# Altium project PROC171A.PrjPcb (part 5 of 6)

## Sheet PROC171_Ehernet_RJ45_2.SchDoc
size 431 x 279 mm; Date: Not shown in title block; ApprovedBy: Not shown in title block; CheckedBy: Not shown in title block; Author: Not shown in title block; CompanyName: Not shown in title block; Engineer: Not shown in title block; Organization: Not shown in title block; Address1: Not shown in title block; Address2: Not shown in title block; Address3: Not shown in title block; Address4: Not shown in title block; DocumentNumber: 20; Revision: Use project parameter SCH_Rev; SheetNumber: 20; SheetTotal: 27; PageSetup: Record=PageOptions¦CenterHorizontal=True¦CenterVertical=True¦PrintScale=1.00¦XCorrection=1.00¦YCorrection=1.00¦PrintKind=0¦BorderSize=5000000¦LeftOffset=0¦BottomOffset=0¦Orientation=2¦PaperLength=1000¦PaperWidth=1000¦Scale=100¦PaperSource=15¦PrintQuality=600¦MediaType=1¦DitherType=10¦PaperKind=Letter¦PrintScaleMode=1
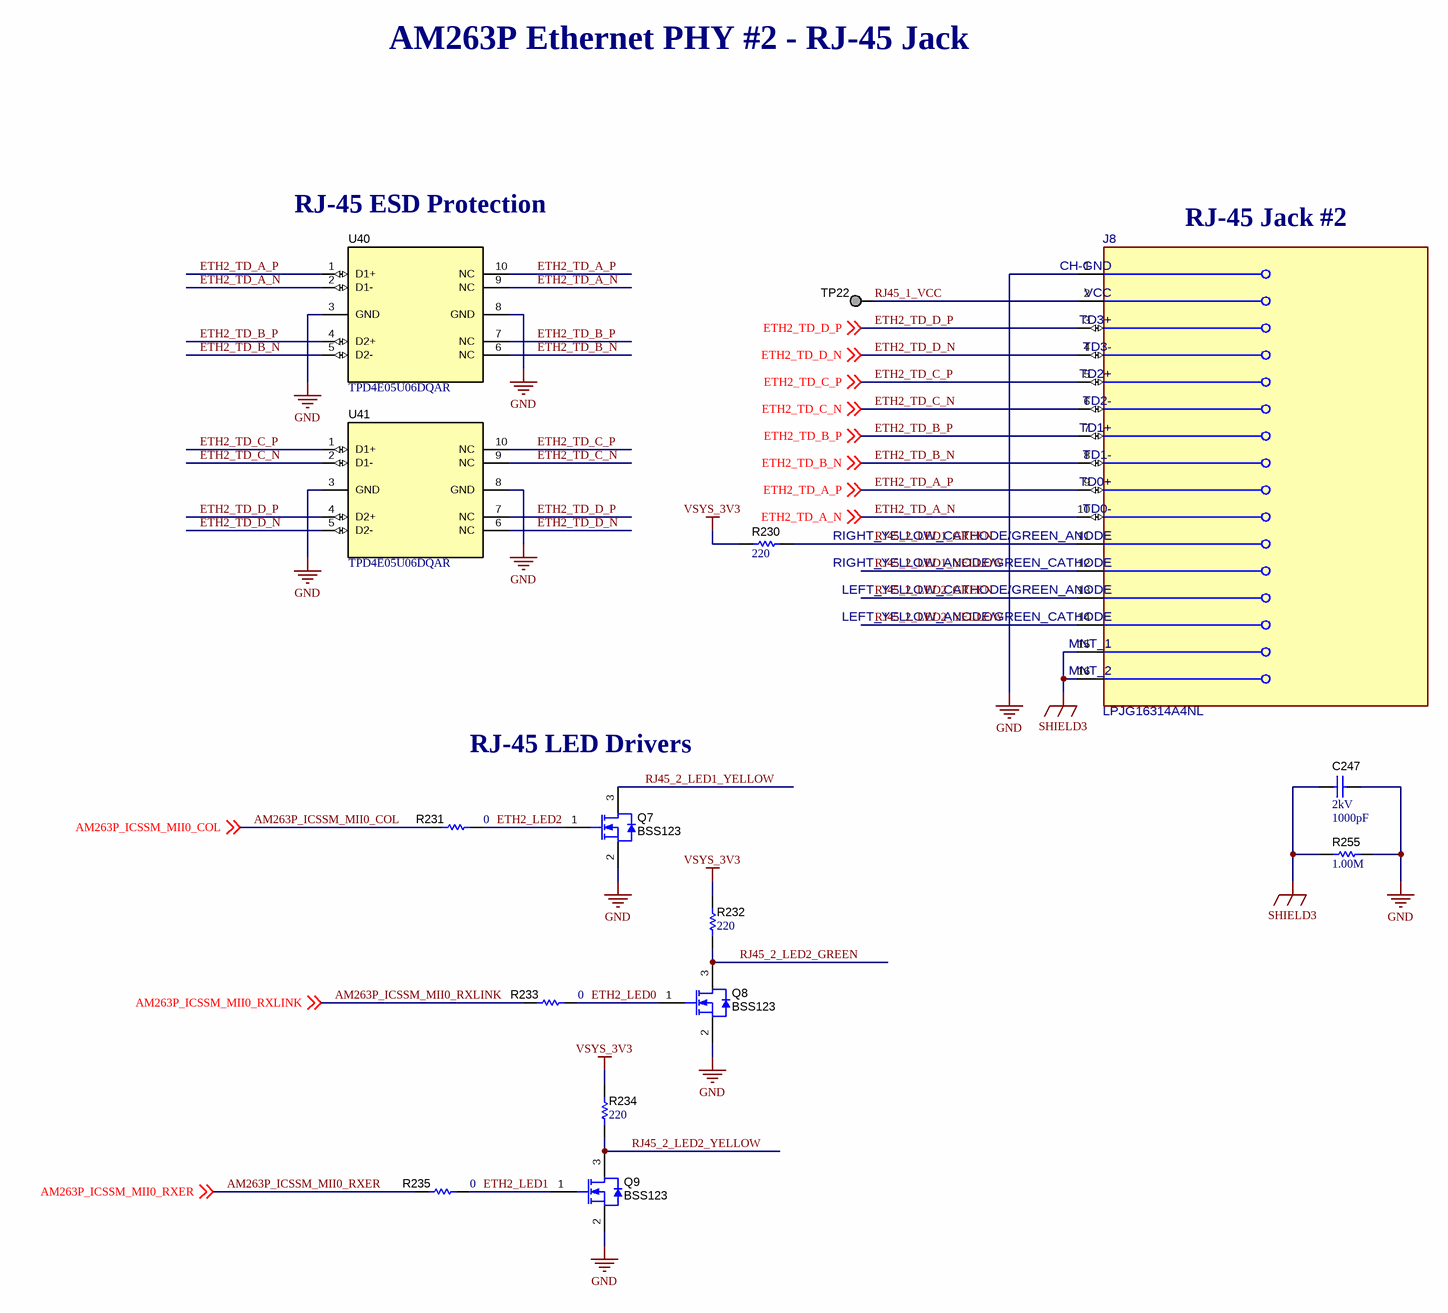
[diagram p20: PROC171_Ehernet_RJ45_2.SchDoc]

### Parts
C247  VDC_V: 2kV  ValueDisplayed: 1000pF  [1808]  (hidden comment: GR442QR73D102KW01L)
J8  LPJG16314A4NL  [FP-LPJG16314A4NL_CONN_RJ45-MFG]
Q7  BSS123  [SOT-23]
Q8  BSS123  [SOT-23]
Q9  BSS123  [SOT-23]
R230  ValueDisplayed: 220  [0402]  (hidden comment: CRCW0402220RJNED)
R231  ValueDisplayed: 0  [0402L]  (hidden comment: ERJ-2GE0R00X)
R232  ValueDisplayed: 220  [0402]  (hidden comment: CRCW0402220RJNED)
R233  ValueDisplayed: 0  [0402L]  (hidden comment: ERJ-2GE0R00X)
R234  ValueDisplayed: 220  [0402]  (hidden comment: CRCW0402220RJNED)
R235  ValueDisplayed: 0  [0402L]  (hidden comment: ERJ-2GE0R00X)
R255  ValueDisplayed: 1.00M  [0805_HV]  (hidden comment: ERJ-6ENF1004V)
TP22  TESTPOINT  [TP_25MIL-SMT]  (value not drawn)  (no BOM)
U40  TPD4E05U06DQAR  [DQA0010A]
U41  TPD4E05U06DQAR  [DQA0010A]

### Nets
GND: C247.1 J8.1(CH-GND) Q7.2(S) Q8.2(S) Q9.2(S) R255.2 U40.3(GND) U40.8(GND) U41.3(GND) U41.8(GND)
SHIELD3: C247.2 J8.15(MNT_1) J8.16(MNT_2) R255.1
VSYS_3V3: R230.1 R232.2 R234.2
AM263P_ICSSM_MII0_COL: R231.2 ; off-sheet AM263P_ICSSM_MII0_COL
AM263P_ICSSM_MII0_RXER: R235.2 ; off-sheet AM263P_ICSSM_MII0_RXER
AM263P_ICSSM_MII0_RXLINK: R233.2 ; off-sheet AM263P_ICSSM_MII0_RXLINK
ETH2_LED0: Q8.1(G) R233.1
ETH2_LED1: Q9.1(G) R235.1
ETH2_LED2: Q7.1(G) R231.1
ETH2_TD_A_N: J8.10(TD0-) U40.2(D1-) U40.9(NC) ; off-sheet ETH2_TD_A_N
ETH2_TD_A_P: J8.9(TD0+) U40.1(D1+) U40.10(NC) ; off-sheet ETH2_TD_A_P
ETH2_TD_B_N: J8.8(TD1-) U40.5(D2-) U40.6(NC) ; off-sheet ETH2_TD_B_N
ETH2_TD_B_P: J8.7(TD1+) U40.4(D2+) U40.7(NC) ; off-sheet ETH2_TD_B_P
ETH2_TD_C_N: J8.6(TD2-) U41.2(D1-) U41.9(NC) ; off-sheet ETH2_TD_C_N
ETH2_TD_C_P: J8.5(TD2+) U41.1(D1+) U41.10(NC) ; off-sheet ETH2_TD_C_P
ETH2_TD_D_N: J8.4(TD3-) U41.5(D2-) U41.6(NC) ; off-sheet ETH2_TD_D_N
ETH2_TD_D_P: J8.3(TD3+) U41.4(D2+) U41.7(NC) ; off-sheet ETH2_TD_D_P
RJ45_1_VCC: J8.2(VCC) TP22.1
RJ45_2_LED1_GREEN: J8.11(RIGHT_YELLOW_CATHODE/GREEN_ANODE) R230.2
RJ45_2_LED1_YELLOW: J8.12(RIGHT_YELLOW_ANODE/GREEN_CATHODE) Q7.3(D)
RJ45_2_LED2_GREEN: J8.13(LEFT_YELLOW_CATHODE/GREEN_ANODE) Q8.3(D) R232.1
RJ45_2_LED2_YELLOW: J8.14(LEFT_YELLOW_ANODE/GREEN_CATHODE) Q9.3(D) R234.1

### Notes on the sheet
- AM263P Ethernet PHY #2 - RJ-45 Jack
- RJ-45 ESD Protection
- RJ-45 Jack #2
- RJ-45 LED Drivers

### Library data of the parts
C247 = CMP-0009436-2: CAP, CERM, 1000 pF, 2000 V, +/- 10%, X7R, 1808; Manufacturer: MuRata; TaMin_C: -55°C; Polarized: N; SizeAreaWB_mm2: 16.5; Value1: Unknown; U/M: EA; Value: 1000pF; TaMax_C: 125°C; SizeZ_mm: 2.03; SizeX_mm: 4.5; SizeY_mm: 2; Value2: 2000V; SizeArea_mm2: 9; Cap_F: 1nF; AEC Category: Q200
J8 = CMP-0093483-1: RJ45 Connector with 1000 Base-TX Inetgrated Magnetic; Manufacturer: Link-PP; SizeZ_mm: 13.7mm; AEC Qualified: No; DUT-Pitch_mm: 1.27mm; Conn Gender: Female; Is Female: yes; ContactFinish: Gold; Conn Orientation: Horizontal
Q7-Q9 = CMP-0000947-2: MOSFET, N-CH, 100 V, 0.17 A, SOT-23; Alternate Manufacturer: None; Manufacturer: Fairchild Semiconductor; SizeZ_mm: 1.1; ChType: N; Value2: 1.8 nC; Value1: 1; VdsMax_V: 100V; SizeX_mm: 2.5; SizeY_mm: 3; Vgs_V: 20V; Value: 100V; Rdson45_ohm: 10; SizeArea_mm2: 7.5; AEC Category: Q101; IdsMax_A: 1.7dA; SizeAreaWB_mm2: 14; U/M: EA; QgTyp_nC: 1.8
R230 R232 R234 = CMP-0026878-3: RES, 220, 5%, 0.063 W, AEC-Q200 Grade 0, 0402; Manufacturer: Vishay-Dale; Power_W: 63mW; TempCo: 200 ppm/C; Value_Code: 220R; Value: 220; EIA_Code: E24; SizeX_mm: 1; SizeY_mm: 0.5; SizeZ_mm: 0.6; Value2: 0.063W; AEC Qualified: Y; VDC_V: 50V; AEC Category: Q200; AEC Grade: 0
R231 R233 R235 = CMP-0026992-3: RES, 0, 5%, 0.1 W, AEC-Q200 Grade 0, 0402; Manufacturer: Panasonic; Power_W: 100mW; TempCo: 600 ppm/C; Value_Code: 0000; Value: 0; EIA_Code: E24; SizeX_mm: 1; SizeY_mm: 0.5; SizeZ_mm: 0.6; Value2: 0.1W; AEC Qualified: Y; VDC_V: 50V; AEC Category: Q200; SizeAreaWB_mm2: 3
R255 = CMP-0021522-3: RES, 1.00 M, 1%, 0.125 W, AEC-Q200 Grade 0, 0805; Manufacturer: Panasonic; Power_W: 125mW; TempCo: 100 ppm/C; Value_Code: 1M00; Value: 1.00Meg; EIA_Code: E96; Res_ohm: 1M; SizeX_mm: 2; SizeY_mm: 1.25; SizeZ_mm: 1.45; Value2: 0.125W; SizeArea_mm2: 2.5; AEC Qualified: Y; AEC Category: Q200; AEC Grade: 0; SizeAreaWB_mm2: 6.75
TP22 = CMP-0078143-3: TEST POINT.  No entry in BOM.
U40 U41 = CMP-0073613-3: 4-Channel Ultra-Low-Capacitance IEC ESD Protection Diode, DQA0010A (USON-10); Alternate Manufacturer: Texas Instruments; Green_Lifecycle: Active; SizeAreaWB_mm2: 7.0; Green_REACh: Passed; SizeZ_mm: 0.55; SizeX_mm: 1.0; SizeY_mm: 2.5; CompType: IC; AEC Category: Q200; AEC Qualified: N

## Sheet PROC171_Boosterpack_Headers.SchDoc
size 431 x 279 mm; Date: Not shown in title block; ApprovedBy: Not shown in title block; CheckedBy: Not shown in title block; Author: Not shown in title block; CompanyName: Not shown in title block; Engineer: Not shown in title block; Organization: Not shown in title block; Address1: Not shown in title block; Address2: Not shown in title block; Address3: Not shown in title block; Address4: Not shown in title block; DocumentNumber: 21; Revision: Use project parameter SCH_Rev; SheetNumber: 21; SheetTotal: 27; PageSetup: Record=PageOptions¦CenterHorizontal=True¦CenterVertical=True¦PrintScale=1.00¦XCorrection=1.00¦YCorrection=1.00¦PrintKind=0¦BorderSize=5000000¦LeftOffset=0¦BottomOffset=0¦Orientation=2¦PaperLength=1000¦PaperWidth=1000¦Scale=100¦PaperSource=15¦PrintQuality=600¦MediaType=1¦DitherType=10¦PaperKind=Letter¦PrintScaleMode=1
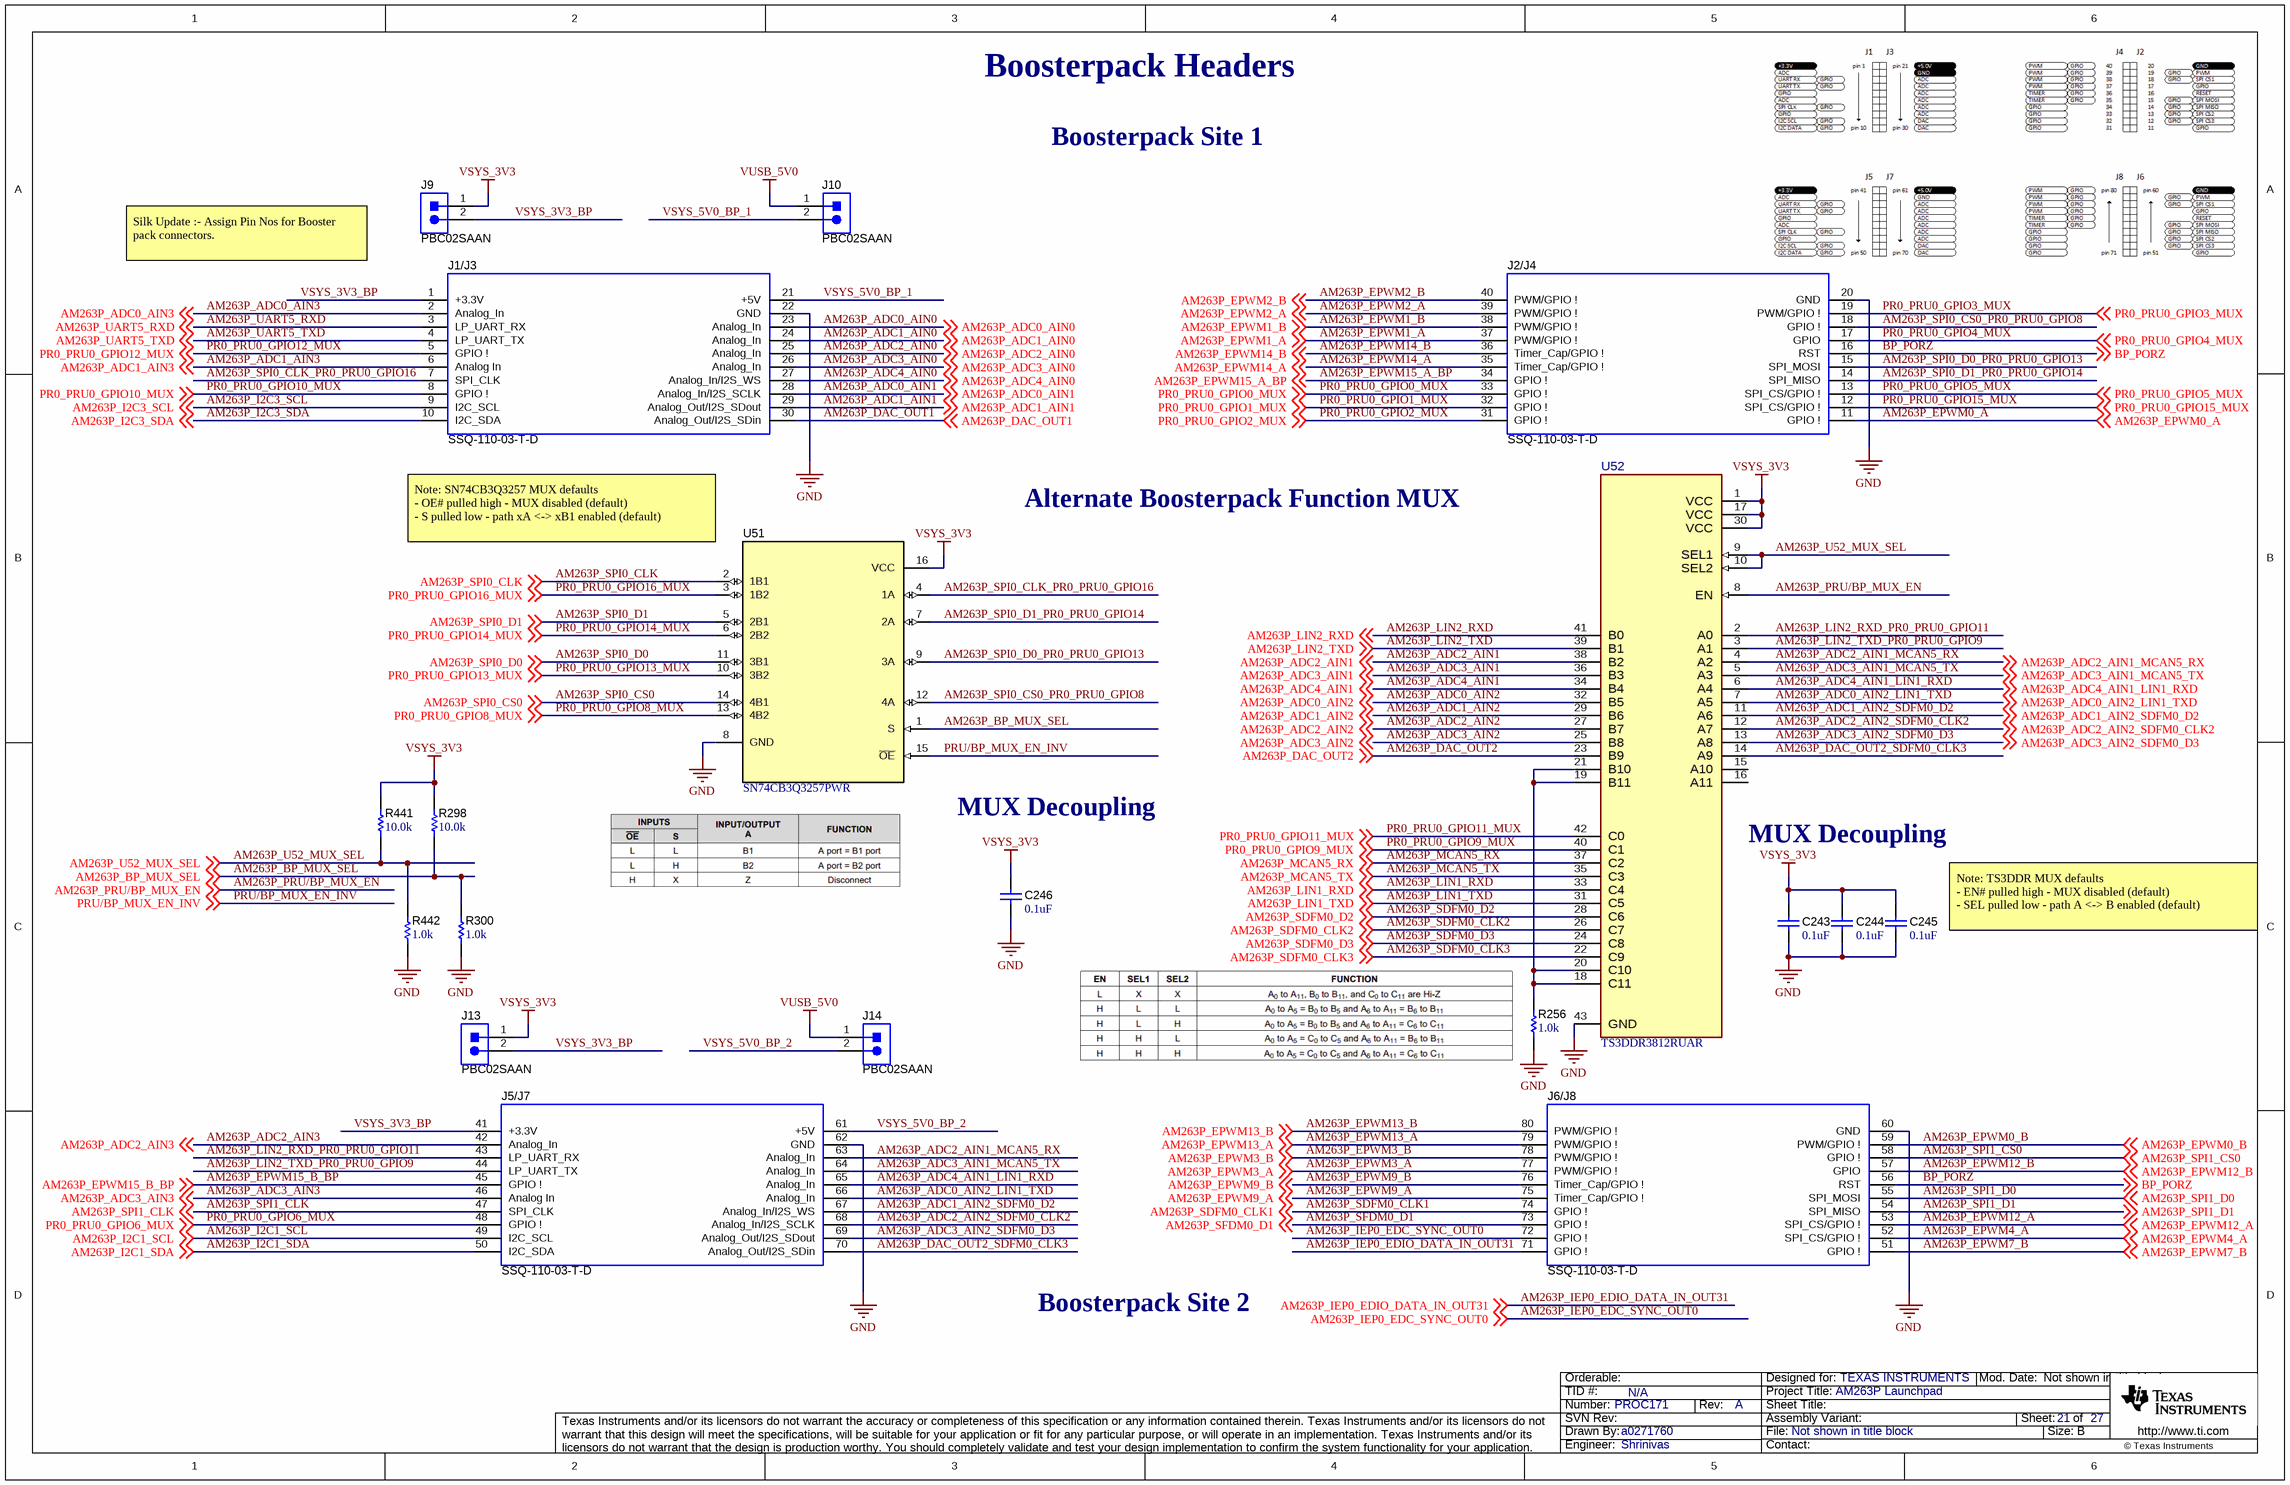
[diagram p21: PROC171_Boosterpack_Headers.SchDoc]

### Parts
C243  ValueDisplayed: 0.1uF  [0402]  (hidden comment: GRM155R71E104KE14D)
C244  ValueDisplayed: 0.1uF  [0402]  (hidden comment: GRM155R71E104KE14D)
C245  ValueDisplayed: 0.1uF  [0402]  (hidden comment: GRM155R71E104KE14D)
C246  ValueDisplayed: 0.1uF  [0402]  (hidden comment: GRM155R71E104KE14D)
J1/J3  SSQ-110-03-T-D  [BoosterPack_40pin_J1J3]
J2/J4  SSQ-110-03-T-D  [BoosterPack_40pin_J2J4]
J5/J7  SSQ-110-03-T-D  [BoosterPack_40pin_J5J7]
J6/J8  SSQ-110-03-T-D  [BoosterPack_40pin_J6J8]
J9  PBC02SAAN  [Sullins_PBC02SAAN]
J10  PBC02SAAN  [Sullins_PBC02SAAN]
J13  PBC02SAAN  [Sullins_PBC02SAAN]
J14  PBC02SAAN  [Sullins_PBC02SAAN]
R256  ValueDisplayed: 1.0k  [0402]  (hidden comment: ERJ-2GEJ102X)
R298  ValueDisplayed: 10.0k  [0402]  (hidden comment: ERJ-2RKF1002X)
R300  ValueDisplayed: 1.0k  [0402]  (hidden comment: ERJ-2GEJ102X)
R441  ValueDisplayed: 10.0k  [0402]  (hidden comment: ERJ-2RKF1002X)
R442  ValueDisplayed: 1.0k  [0402]  (hidden comment: ERJ-2GEJ102X)
U51  SN74CB3Q3257PWR  [PW0016A_L]
U52  TS3DDR3812RUAR  [RUA0042A-MFG]

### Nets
GND: C243.1 C244.1 C245.1 C246.1 J1/J3.22(GND) J2/J4.20(GND) J5/J7.62(GND) J6/J8.60(GND) R256.1 R300.1 R442.1 U51.8(GND) U52.43(GND)
VSYS_3V3: C243.2 C244.2 C245.2 C246.2 J9.1 J13.1 R298.1 R441.1 U51.16(VCC) U52.1(VCC) U52.17(VCC) U52.30(VCC)
VUSB_5V0: J10.1 J14.1
AM263P_ADC0_AIN0: J1/J3.23(Analog_In) ; off-sheet AM263P_ADC0_AIN0
AM263P_ADC0_AIN1: J1/J3.28(Analog_In/I2S_SCLK) ; off-sheet AM263P_ADC0_AIN1
AM263P_ADC0_AIN2: U52.32(B5) ; off-sheet AM263P_ADC0_AIN2
AM263P_ADC0_AIN2_LIN1_TXD: J5/J7.66(Analog_In) U52.7(A5) ; off-sheet AM263P_ADC0_AIN2_LIN1_TXD
AM263P_ADC0_AIN3: J1/J3.2(Analog_In) ; off-sheet AM263P_ADC0_AIN3
AM263P_ADC1_AIN0: J1/J3.24(Analog_In) ; off-sheet AM263P_ADC1_AIN0
AM263P_ADC1_AIN1: J1/J3.29(Analog_Out/I2S_SDout) ; off-sheet AM263P_ADC1_AIN1
AM263P_ADC1_AIN2: U52.29(B6) ; off-sheet AM263P_ADC1_AIN2
AM263P_ADC1_AIN2_SDFM0_D2: J5/J7.67(Analog_In/I2S_WS) U52.11(A6) ; off-sheet AM263P_ADC1_AIN2_SDFM0_D2
AM263P_ADC1_AIN3: J1/J3.6(Analog_In) ; off-sheet AM263P_ADC1_AIN3
AM263P_ADC2_AIN0: J1/J3.25(Analog_In) ; off-sheet AM263P_ADC2_AIN0
AM263P_ADC2_AIN1: U52.38(B2) ; off-sheet AM263P_ADC2_AIN1
AM263P_ADC2_AIN1_MCAN5_RX: J5/J7.63(Analog_In) U52.4(A2) ; off-sheet AM263P_ADC2_AIN1_MCAN5_RX
AM263P_ADC2_AIN2: U52.27(B7) ; off-sheet AM263P_ADC2_AIN2
AM263P_ADC2_AIN2_SDFM0_CLK2: J5/J7.68(Analog_In/I2S_SCLK) U52.12(A7) ; off-sheet AM263P_ADC2_AIN2_SDFM0_CLK2
AM263P_ADC2_AIN3: J5/J7.42(Analog_In) ; off-sheet AM263P_ADC2_AIN3
AM263P_ADC3_AIN0: J1/J3.26(Analog_In) ; off-sheet AM263P_ADC3_AIN0
AM263P_ADC3_AIN1: U52.36(B3) ; off-sheet AM263P_ADC3_AIN1
AM263P_ADC3_AIN1_MCAN5_TX: J5/J7.64(Analog_In) U52.5(A3) ; off-sheet AM263P_ADC3_AIN1_MCAN5_TX
AM263P_ADC3_AIN2: U52.25(B8) ; off-sheet AM263P_ADC3_AIN2
AM263P_ADC3_AIN2_SDFM0_D3: J5/J7.69(Analog_Out/I2S_SDout) U52.13(A8) ; off-sheet AM263P_ADC3_AIN2_SDFM0_D3
AM263P_ADC3_AIN3: J5/J7.46(Analog_In) ; off-sheet AM263P_ADC3_AIN3
AM263P_ADC4_AIN0: J1/J3.27(Analog_In/I2S_WS) ; off-sheet AM263P_ADC4_AIN0
AM263P_ADC4_AIN1: U52.34(B4) ; off-sheet AM263P_ADC4_AIN1
AM263P_ADC4_AIN1_LIN1_RXD: J5/J7.65(Analog_In) U52.6(A4) ; off-sheet AM263P_ADC4_AIN1_LIN1_RXD
AM263P_BP_MUX_SEL: R298.2 R300.2 U51.1(S) ; off-sheet AM263P_BP_MUX_SEL
AM263P_DAC_OUT1: J1/J3.30(Analog_Out/I2S_SDin) ; off-sheet AM263P_DAC_OUT1
AM263P_DAC_OUT2: U52.23(B9) ; off-sheet AM263P_DAC_OUT2
AM263P_DAC_OUT2_SDFM0_CLK3: J5/J7.70(Analog_Out/I2S_SDin) U52.14(A9)
AM263P_EPWM0_A: J2/J4.11(GPIO_!) ; off-sheet AM263P_EPWM0_A
AM263P_EPWM0_B: J6/J8.59(PWM/GPIO_!) ; off-sheet AM263P_EPWM0_B
AM263P_EPWM1_A: J2/J4.37(PWM/GPIO_!) ; off-sheet AM263P_EPWM1_A
AM263P_EPWM1_B: J2/J4.38(PWM/GPIO_!) ; off-sheet AM263P_EPWM1_B
AM263P_EPWM2_A: J2/J4.39(PWM/GPIO_!) ; off-sheet AM263P_EPWM2_A
AM263P_EPWM2_B: J2/J4.40(PWM/GPIO_!) ; off-sheet AM263P_EPWM2_B
AM263P_EPWM3_A: J6/J8.77(PWM/GPIO_!) ; off-sheet AM263P_EPWM3_A
AM263P_EPWM3_B: J6/J8.78(PWM/GPIO_!) ; off-sheet AM263P_EPWM3_B
AM263P_EPWM4_A: J6/J8.52(SPI_CS/GPIO_!) ; off-sheet AM263P_EPWM4_A
AM263P_EPWM7_B: J6/J8.51(GPIO_!) ; off-sheet AM263P_EPWM7_B
AM263P_EPWM9_A: J6/J8.75(Timer_Cap/GPIO_!) ; off-sheet AM263P_EPWM9_A
AM263P_EPWM9_B: J6/J8.76(Timer_Cap/GPIO_!) ; off-sheet AM263P_EPWM9_B
AM263P_EPWM12_A: J6/J8.53(SPI_CS/GPIO_!) ; off-sheet AM263P_EPWM12_A
AM263P_EPWM12_B: J6/J8.57(GPIO) ; off-sheet AM263P_EPWM12_B
AM263P_EPWM13_A: J6/J8.79(PWM/GPIO_!) ; off-sheet AM263P_EPWM13_A
AM263P_EPWM13_B: J6/J8.80(PWM/GPIO_!) ; off-sheet AM263P_EPWM13_B
AM263P_EPWM14_A: J2/J4.35(Timer_Cap/GPIO_!) ; off-sheet AM263P_EPWM14_A
AM263P_EPWM14_B: J2/J4.36(Timer_Cap/GPIO_!) ; off-sheet AM263P_EPWM14_B
AM263P_EPWM15_A_BP: J2/J4.34(GPIO_!) ; off-sheet AM263P_EPWM15_A_BP
AM263P_EPWM15_B_BP: J5/J7.45(GPIO_!) ; off-sheet AM263P_EPWM15_B_BP
AM263P_I2C1_SCL: J5/J7.49(I2C_SCL) ; off-sheet AM263P_I2C1_SCL
AM263P_I2C1_SDA: J5/J7.50(I2C_SDA) ; off-sheet AM263P_I2C1_SDA
AM263P_I2C3_SCL: J1/J3.9(I2C_SCL) ; off-sheet AM263P_I2C3_SCL
AM263P_I2C3_SDA: J1/J3.10(I2C_SDA) ; off-sheet AM263P_I2C3_SDA
AM263P_IEP0_EDC_SYNC_OUT0: J6/J8.72(GPIO_!) ; off-sheet AM263P_IEP0_EDC_SYNC_OUT0
AM263P_IEP0_EDIO_DATA_IN_OUT31: J6/J8.71(GPIO_!) ; off-sheet AM263P_IEP0_EDIO_DATA_IN_OUT31
AM263P_LIN1_RXD: U52.33(C4) ; off-sheet AM263P_LIN1_RXD
AM263P_LIN1_TXD: U52.31(C5) ; off-sheet AM263P_LIN1_TXD
AM263P_LIN2_RXD: U52.41(B0) ; off-sheet AM263P_LIN2_RXD
AM263P_LIN2_RXD_PR0_PRU0_GPIO11: J5/J7.43(LP_UART_RX) U52.2(A0)
AM263P_LIN2_TXD: U52.39(B1) ; off-sheet AM263P_LIN2_TXD
AM263P_LIN2_TXD_PR0_PRU0_GPIO9: J5/J7.44(LP_UART_TX) U52.3(A1)
AM263P_MCAN5_RX: U52.37(C2) ; off-sheet AM263P_MCAN5_RX
AM263P_MCAN5_TX: U52.35(C3) ; off-sheet AM263P_MCAN5_TX
AM263P_PRU/BP_MUX_EN: U52.8(EN) ; off-sheet AM263P_PRU/BP_MUX_EN
AM263P_SDFM0_CLK1: J6/J8.74(GPIO_!) ; off-sheet AM263P_SDFM0_CLK1
AM263P_SDFM0_CLK2: U52.26(C7) ; off-sheet AM263P_SDFM0_CLK2
AM263P_SDFM0_CLK3: U52.22(C9) ; off-sheet AM263P_SDFM0_CLK3
AM263P_SDFM0_D2: U52.28(C6) ; off-sheet AM263P_SDFM0_D2
AM263P_SDFM0_D3: U52.24(C8) ; off-sheet AM263P_SDFM0_D3
AM263P_SFDM0_D1: J6/J8.73(GPIO_!) ; off-sheet AM263P_SFDM0_D1
AM263P_SPI0_CLK: U51.2(1B1) ; off-sheet AM263P_SPI0_CLK
AM263P_SPI0_CLK_PR0_PRU0_GPIO16: J1/J3.7(SPI_CLK) U51.4(1A)
AM263P_SPI0_CS0: U51.14(4B1) ; off-sheet AM263P_SPI0_CS0
AM263P_SPI0_CS0_PR0_PRU0_GPIO8: J2/J4.18(GPIO_!) U51.12(4A)
AM263P_SPI0_D0: U51.11(3B1) ; off-sheet AM263P_SPI0_D0
AM263P_SPI0_D0_PR0_PRU0_GPIO13: J2/J4.15(SPI_MOSI) U51.9(3A)
AM263P_SPI0_D1: U51.5(2B1) ; off-sheet AM263P_SPI0_D1
AM263P_SPI0_D1_PR0_PRU0_GPIO14: J2/J4.14(SPI_MISO) U51.7(2A)
AM263P_SPI1_CLK: J5/J7.47(SPI_CLK) ; off-sheet AM263P_SPI1_CLK
AM263P_SPI1_CS0: J6/J8.58(GPIO_!) ; off-sheet AM263P_SPI1_CS0
AM263P_SPI1_D0: J6/J8.55(SPI_MOSI) ; off-sheet AM263P_SPI1_D0
AM263P_SPI1_D1: J6/J8.54(SPI_MISO) ; off-sheet AM263P_SPI1_D1
AM263P_U52_MUX_SEL: R441.2 R442.2 U52.9(SEL1) U52.10(SEL2) ; off-sheet AM263P_U52_MUX_SEL
AM263P_UART5_RXD: J1/J3.3(LP_UART_RX) ; off-sheet AM263P_UART5_RXD
AM263P_UART5_TXD: J1/J3.4(LP_UART_TX) ; off-sheet AM263P_UART5_TXD
BP_PORZ: J2/J4.16(RST) J6/J8.56(RST) ; off-sheet BP_PORZ
PR0_PRU0_GPIO0_MUX: J2/J4.33(GPIO_!) ; off-sheet PR0_PRU0_GPIO0_MUX
PR0_PRU0_GPIO1_MUX: J2/J4.32(GPIO_!) ; off-sheet PR0_PRU0_GPIO1_MUX
PR0_PRU0_GPIO2_MUX: J2/J4.31(GPIO_!) ; off-sheet PR0_PRU0_GPIO2_MUX
PR0_PRU0_GPIO3_MUX: J2/J4.19(PWM/GPIO_!) ; off-sheet PR0_PRU0_GPIO3_MUX
PR0_PRU0_GPIO4_MUX: J2/J4.17(GPIO) ; off-sheet PR0_PRU0_GPIO4_MUX
PR0_PRU0_GPIO5_MUX: J2/J4.13(SPI_CS/GPIO_!) ; off-sheet PR0_PRU0_GPIO5_MUX
PR0_PRU0_GPIO6_MUX: J5/J7.48(GPIO_!) ; off-sheet PR0_PRU0_GPIO6_MUX
PR0_PRU0_GPIO8_MUX: U51.13(4B2) ; off-sheet PR0_PRU0_GPIO8_MUX
PR0_PRU0_GPIO9_MUX: U52.40(C1) ; off-sheet PR0_PRU0_GPIO9_MUX
PR0_PRU0_GPIO10_MUX: J1/J3.8(GPIO_!) ; off-sheet PR0_PRU0_GPIO10_MUX
PR0_PRU0_GPIO11_MUX: U52.42(C0) ; off-sheet PR0_PRU0_GPIO11_MUX
PR0_PRU0_GPIO12_MUX: J1/J3.5(GPIO_!) ; off-sheet PR0_PRU0_GPIO12_MUX
PR0_PRU0_GPIO13_MUX: U51.10(3B2) ; off-sheet PR0_PRU0_GPIO13_MUX
PR0_PRU0_GPIO14_MUX: U51.6(2B2) ; off-sheet PR0_PRU0_GPIO14_MUX
PR0_PRU0_GPIO15_MUX: J2/J4.12(SPI_CS/GPIO_!) ; off-sheet PR0_PRU0_GPIO15_MUX
PR0_PRU0_GPIO16_MUX: U51.3(1B2) ; off-sheet PR0_PRU0_GPIO16_MUX
PRU/BP_MUX_EN_INV: U51.15(~{OE}) ; off-sheet PRU/BP_MUX_EN_INV
VSYS_3V3_BP: J1/J3.1(+3.3V) J5/J7.41(+3.3V) J9.2 J13.2
VSYS_5V0_BP_1: J1/J3.21(+5V) J10.2
VSYS_5V0_BP_2: J5/J7.61(+5V) J14.2
NetR256_2: R256.2 U52.18(C11) U52.19(B11) U52.20(C10) U52.21(B10)

Not connected (* = marked no-connect by the designer): U52 15(A10) 16(A11)

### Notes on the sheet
- Boosterpack Headers
- Boosterpack Site 1
- Silk Update :- Assign Pin Nos for Booster pack connectors.
- Note: SN74CB3Q3257 MUX defaults
  - OE# pulled high - MUX disabled (default)
  - S pulled low - path xA <-> xB1 enabled (default)
- Alternate Boosterpack Function MUX
- MUX Decoupling
- (near U52) MUX Decoupling
- Note: TS3DDR MUX defaults
  - EN# pulled high - MUX disabled (default)
  - SEL pulled low - path A <-> B enabled (default)
- Boosterpack Site 2

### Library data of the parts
C243-C246 = CMP-0006659-2: CAP, CERM, 0.1 uF, 25 V, +/- 10%, X7R, 0402; Manufacturer: MuRata; TaMin_C: -55°C; Polarized: N; SizeAreaWB_mm2: 3; U/M: EA; Value: 0.1uF; TaMax_C: 125°C; SizeZ_mm: 0.6; SizeX_mm: 1; SizeY_mm: 0.5; Value2: 25V; Cap_F: 100nF; AEC Category: Q200; Value1: Unknown
J1/J3 = CMP-0003837-4: Receptacle, 2.54mm, 10x2, Tin, TH; Alternate PartNumber: CRD-081413-A-G; Manufacturer: Samtec; Alternate Manufacturer: Major League Electronics; Note: Booster Pack 40 pin J1 and J3; Green_Lifecycle: Active; Green_REACh: Incomplete
J2/J4 = CMP-0078266-4: Receptacle, 2.54mm, 10x2, Tin, TH; Alternate PartNumber: CRD-081413-A-G; Manufacturer: Samtec; Alternate Manufacturer: Major League Electronics; Note: Booster Pack 40 pin J2 and J4; Green_REACh: Incomplete; Green_Lifecycle: Active
J5/J7 = CMP-0081070-3: Receptacle, 2.54mm, 10x2, Tin, TH; Alternate PartNumber: CRD-081413-A-G; Manufacturer: Samtec; Alternate Manufacturer: Major League Electronics; Note: Booster Pack 40 pin J5 and J7; Green_REACh: Incomplete; Green_Lifecycle: Active
J6/J8 = CMP-0081071-3: Receptacle, 2.54mm, 10x2, Tin, TH; Alternate PartNumber: CRD-081413-A-G; Manufacturer: Samtec; Alternate Manufacturer: Major League Electronics; Note: Booster Pack 40 pin J6 and J8; Green_REACh: Incomplete; Green_Lifecycle: Active
J9 J10 J13 J14 = CMP-0054566-1: Header, 100mil, 2x1, Gold, TH; Manufacturer: Sullins Connector Solutions; CNHeader: TRUE; Current_A: 3A; Green_Lifecycle: Active; Shrouded: N; Gender: Male; Green_REACh: Passed; Voltage_V: 1.8kV; Row_Count: 1; Pitch_mm: 2.54; CT: FALSE; Cert_UL: Y
R256 R300 R442 = CMP-0078193-1: RES, 1.0 k, 5%, 0.1 W, AEC-Q200 Grade 0, 0402; Manufacturer: Panasonic; Value_Code: 1k00; SizeArea_mm2: 0.5; AEC Qualified: Y; AEC Category: Q200; Res_ohm: 1k; Value: 1.0k; SizeZ_mm: 0.6; Green_REACh: Passed; EIA_Code: E24; TempCo: 200 ppm/C; AEC Grade: 0; Power_W: 100mW; VDC_V: 50V; Value2: 0.1W; Green_Lifecycle: Active; U/M: EA; SizeX_mm: 1
R298 R441 = CMP-0026658-1: RES, 10.0 k, 1%, 0.1 W, 0402; Manufacturer: Panasonic; Power_W: 100mW; TempCo: 100 ppm/C; Value_Code: 10k0; U/M: EA; Value: 10.0k; EIA_Code: E96; Res_ohm: 10k; SizeX_mm: 1; SizeY_mm: 0.5; SizeZ_mm: 0.6; Value2: 0.1W; VDC_V: 50V; AEC Category: Q200
U51 = CMP-0076540-1: 4-Bit One-of-2 FET Multiplexer/Demultiplexer 2.5-V/3.3-V Low-Voltage, High-Bandwidth Bus Switch, PW0016A (TSSOP-16); Manufacturer: Texas Instruments; SizeAreaWB_mm2: 58.8; SizeArea_mm2: 32.0; SizeZ_mm: 1.2; SizeY_mm: 5.0; U/M: EA; CompType: IC; SizeX_mm: 6.4
U52 = CMP-0093539-2: IC MUX/DEMUX DDR3 1:2 42WQFN; Manufacturer: Texas Instruments; TaMax_C: +85°C; TaMin_C: -40°C; On State Resistance: 8Ω; SizeZ_mm: 0.8mm; Min Supply Voltage: 3V; Standoff Height: 0mm; Max Supply Voltage: 3.6V; AEC Qualified: No; PositionCount: 12; -3Db Bandwith: 1.675GHz; Nominal Supply Current: 300uA; AEC Category: Q200

## Sheet PROC171_Breakout_Headers.SchDoc
size 431 x 279 mm; Date: Not shown in title block; ApprovedBy: Not shown in title block; CheckedBy: Not shown in title block; Author: Not shown in title block; CompanyName: Not shown in title block; Engineer: Not shown in title block; Organization: Not shown in title block; Address1: Not shown in title block; Address2: Not shown in title block; Address3: Not shown in title block; Address4: Not shown in title block; DocumentNumber: 22; Revision: Use project parameter SCH_Rev; SheetNumber: 22; SheetTotal: 27; PageSetup: Record=PageOptions¦CenterHorizontal=True¦CenterVertical=True¦PrintScale=1.00¦XCorrection=1.00¦YCorrection=1.00¦PrintKind=0¦BorderSize=5000000¦LeftOffset=0¦BottomOffset=0¦Orientation=2¦PaperLength=1000¦PaperWidth=1000¦Scale=100¦PaperSource=15¦PrintQuality=600¦MediaType=1¦DitherType=10¦PaperKind=Letter¦PrintScaleMode=1
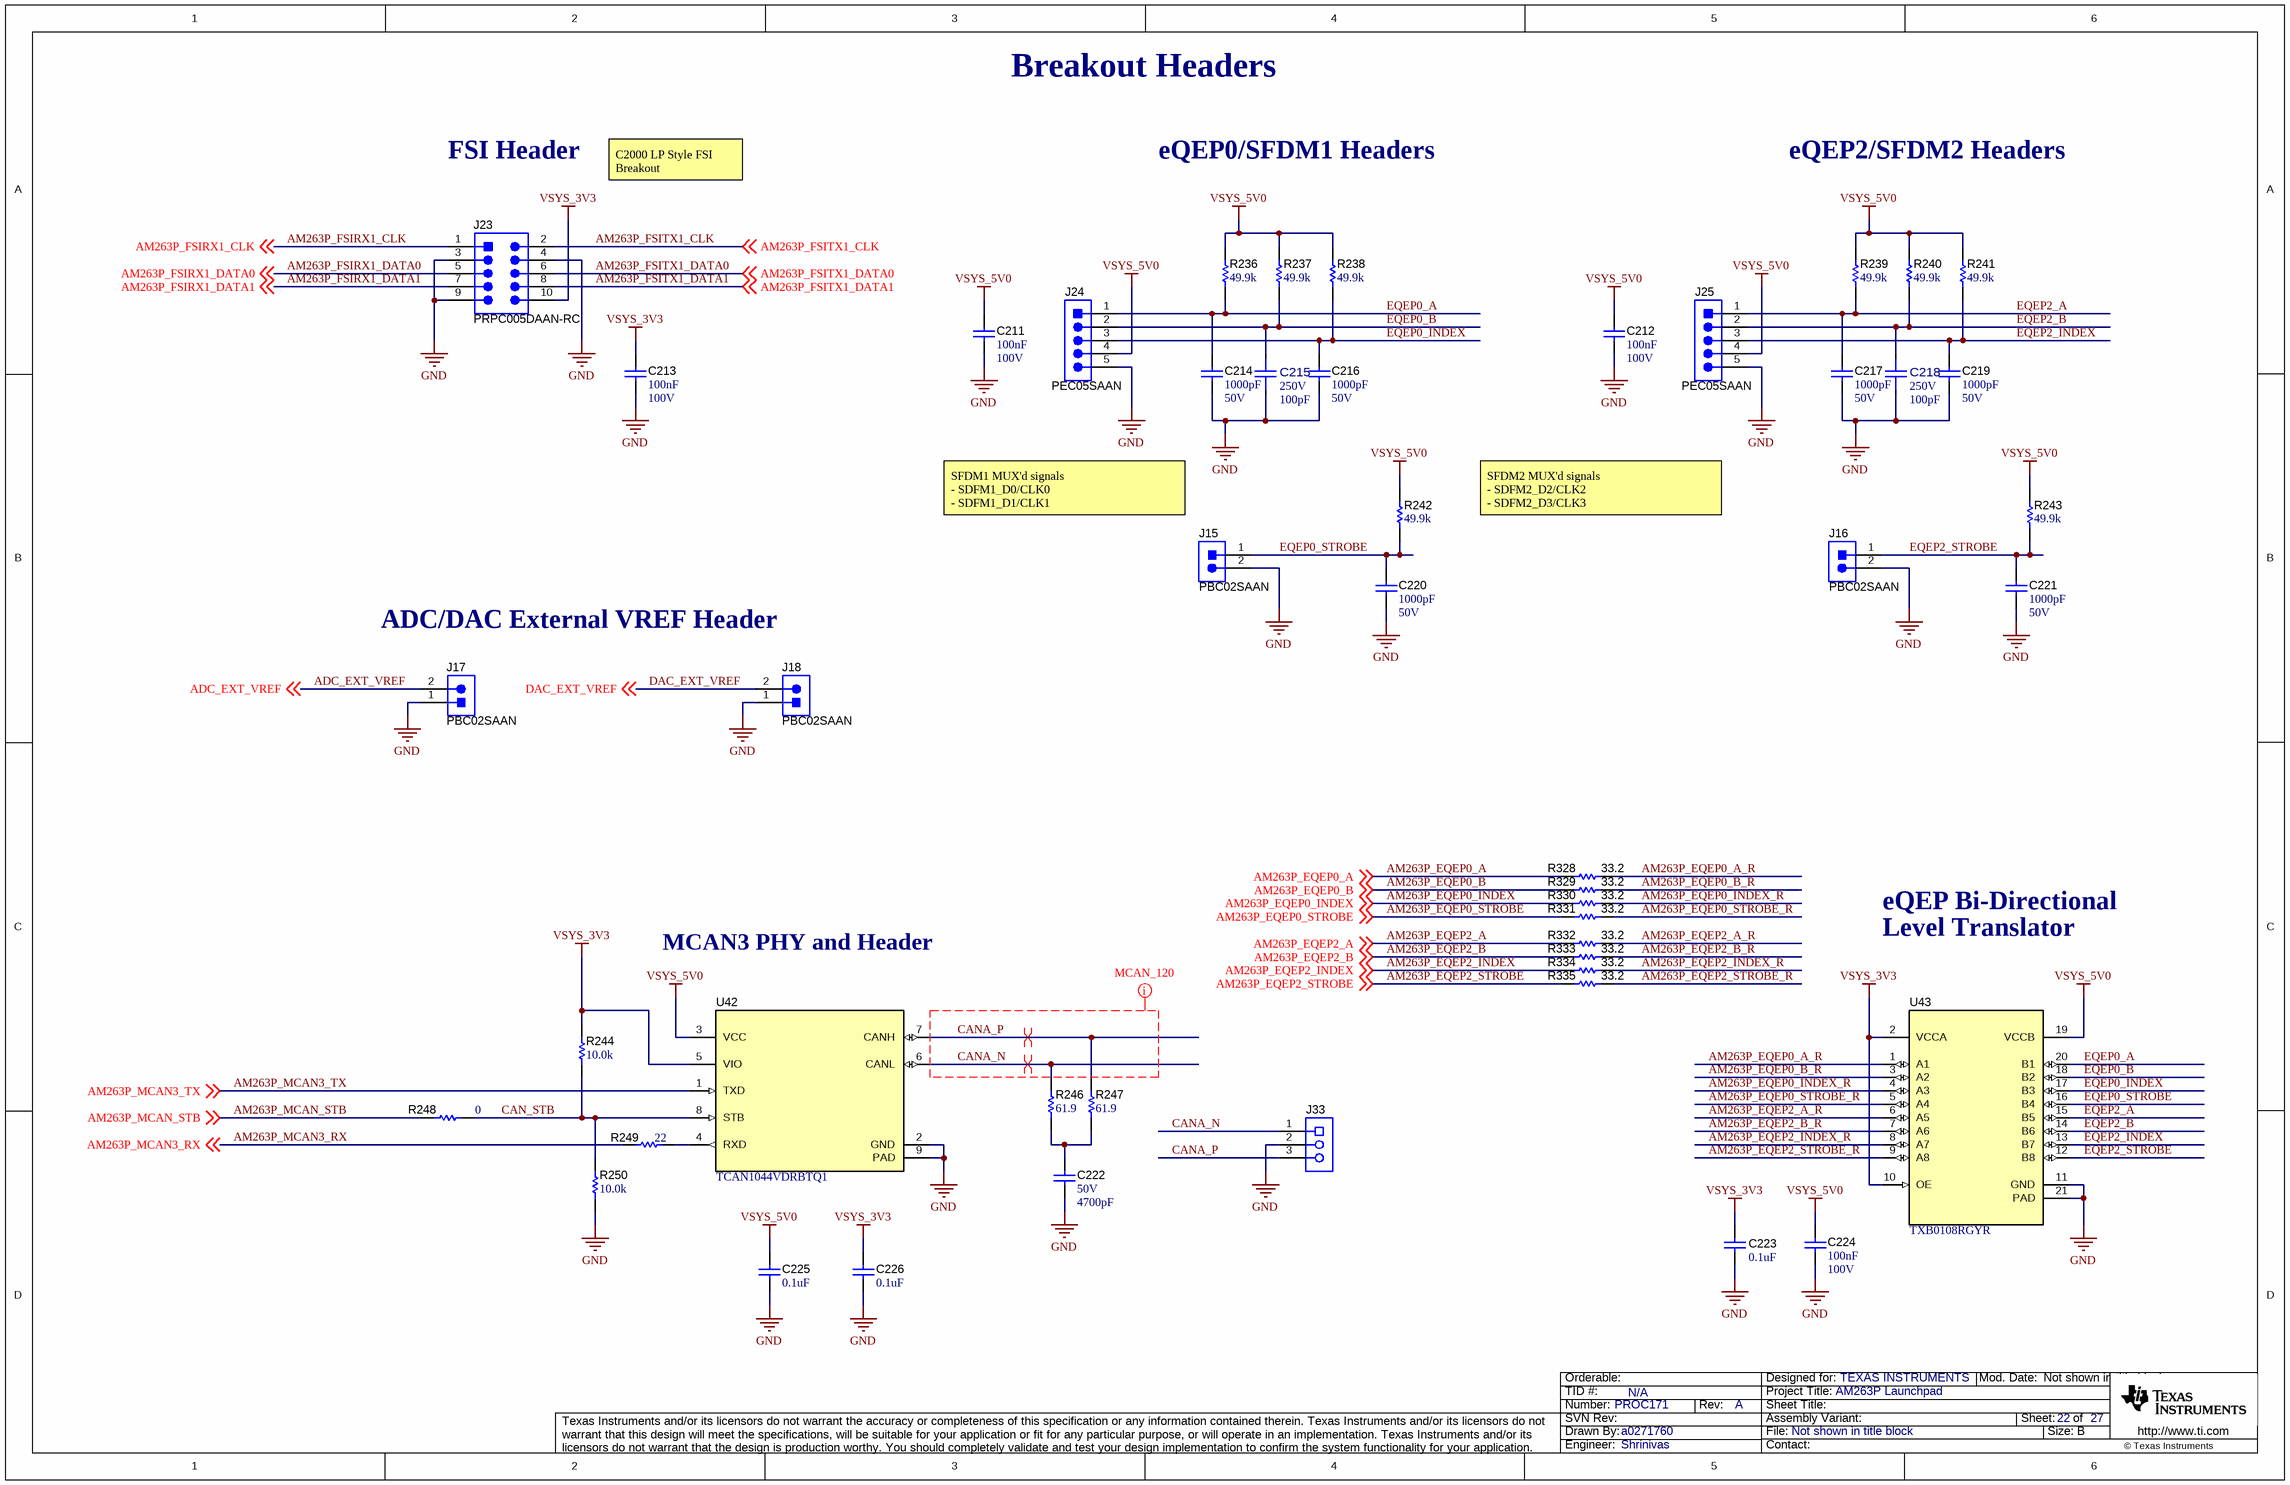
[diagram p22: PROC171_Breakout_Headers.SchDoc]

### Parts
C211  Cap_F: 100nF  VDC_V: 100V  [0603]  (hidden comment: GRM188R72A104KA35D)
C212  Cap_F: 100nF  VDC_V: 100V  [0603]  (hidden comment: GRM188R72A104KA35D)
C213  Cap_F: 100nF  VDC_V: 100V  [0603]  (hidden comment: GRM188R72A104KA35D)
C214  ValueDisplayed: 1000pF  VDC_V: 50V  [0603]  (hidden comment: GRM1885C1H102JA01D)
C215  VDC_V: 250V  ValueDisplayed: 100pF  [FP-GQM1875C2E101JB12D_0603-MFG]  (hidden comment: GQM1875C2E101JB12D)
C216  ValueDisplayed: 1000pF  VDC_V: 50V  [0603]  (hidden comment: GRM1885C1H102JA01D)
C217  ValueDisplayed: 1000pF  VDC_V: 50V  [0603]  (hidden comment: GRM1885C1H102JA01D)
C218  VDC_V: 250V  ValueDisplayed: 100pF  [FP-GQM1875C2E101JB12D_0603-MFG]  (hidden comment: GQM1875C2E101JB12D)
C219  ValueDisplayed: 1000pF  VDC_V: 50V  [0603]  (hidden comment: GRM1885C1H102JA01D)
C220  ValueDisplayed: 1000pF  VDC_V: 50V  [0603]  (hidden comment: GRM1885C1H102JA01D)
C221  ValueDisplayed: 1000pF  VDC_V: 50V  [0603]  (hidden comment: GRM1885C1H102JA01D)
C222  VDC_V: 50V  ValueDisplayed: 4700pF  [0402]  (hidden comment: GRM155R71H472KA01D)
C223  ValueDisplayed: 0.1uF  [0402]  (hidden comment: GRM155R71E104KE14D)
C224  Cap_F: 100nF  VDC_V: 100V  [0603]  (hidden comment: GRM188R72A104KA35D)
C225  ValueDisplayed: 0.1uF  [0402]  (hidden comment: GRM155R71E104KE14D)
C226  ValueDisplayed: 0.1uF  [0402]  (hidden comment: GRM155R71E104KE14D)
J15  PBC02SAAN  [Sullins_PBC02SAAN]
J16  PBC02SAAN  [Sullins_PBC02SAAN]
J17  PBC02SAAN  [Sullins_PBC02SAAN]
J18  PBC02SAAN  [Sullins_PBC02SAAN]
J23  PRPC005DAAN-RC  [Sullins_xxPC005DAAN-RC]
J24  PEC05SAAN  [Sullins_PxC05SAAN]
J25  PEC05SAAN  [Sullins_PxC05SAAN]
J33  OSTTE030161  [On-Shore_OSTTE030161]  (value not drawn)
R236  ValueDisplayed: 49.9k  [0402]  (hidden comment: ERJ-2RKF4992X)
R237  ValueDisplayed: 49.9k  [0402]  (hidden comment: ERJ-2RKF4992X)
R238  ValueDisplayed: 49.9k  [0402]  (hidden comment: ERJ-2RKF4992X)
R239  ValueDisplayed: 49.9k  [0402]  (hidden comment: ERJ-2RKF4992X)
R240  ValueDisplayed: 49.9k  [0402]  (hidden comment: ERJ-2RKF4992X)
R241  ValueDisplayed: 49.9k  [0402]  (hidden comment: ERJ-2RKF4992X)
R242  ValueDisplayed: 49.9k  [0402]  (hidden comment: ERJ-2RKF4992X)
R243  ValueDisplayed: 49.9k  [0402]  (hidden comment: ERJ-2RKF4992X)
R244  ValueDisplayed: 10.0k  [0402L]  (hidden comment: CRCW040210K0FKED)
R246  ValueDisplayed: 61.9  [0402L]  (hidden comment: CRCW040261R9FKED)
R247  ValueDisplayed: 61.9  [0402L]  (hidden comment: CRCW040261R9FKED)
R248  ValueDisplayed: 0  [0402L]  (hidden comment: ERJ-2GE0R00X)
R249  ValueDisplayed: 22  [0402]  (hidden comment: CRCW040222R0JNED)
R250  ValueDisplayed: 10.0k  [0402L]  (hidden comment: CRCW040210K0FKED)
R328  ValueDisplayed: 33.2  [0402]  (hidden comment: CRCW040233R2FKED)
R329  ValueDisplayed: 33.2  [0402]  (hidden comment: CRCW040233R2FKED)
R330  ValueDisplayed: 33.2  [0402]  (hidden comment: CRCW040233R2FKED)
R331  ValueDisplayed: 33.2  [0402]  (hidden comment: CRCW040233R2FKED)
R332  ValueDisplayed: 33.2  [0402]  (hidden comment: CRCW040233R2FKED)
R333  ValueDisplayed: 33.2  [0402]  (hidden comment: CRCW040233R2FKED)
R334  ValueDisplayed: 33.2  [0402]  (hidden comment: CRCW040233R2FKED)
R335  ValueDisplayed: 33.2  [0402]  (hidden comment: CRCW040233R2FKED)
U42  TCAN1044VDRBTQ1  [DRB0008J]
U43  TXB0108RGYR  [RGY0020A]

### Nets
GND: C211.2 C212.2 C213.2 C214.2 C215.1 C216.2 C217.2 C218.1 C219.2 C220.2 C221.2 C222.2 C223.1 C224.2 C225.1 C226.1 J15.2 J16.2 J17.1 J18.1 J23.3 J23.4 J23.9 J24.5 J25.5 J33.2 R250.1 U42.2(GND) U42.9(PAD) U43.11(GND) U43.21(PAD)
VSYS_3V3: C213.1 C223.2 C226.2 J23.10 R244.2 U42.5(VIO) U43.2(VCCA) U43.10(OE)
VSYS_5V0: C211.1 C212.1 C224.1 C225.2 J24.4 J25.4 R236.2 R237.2 R238.2 R239.2 R240.2 R241.2 R242.2 R243.2 U42.3(VCC) U43.19(VCCB)
ADC_EXT_VREF: J17.2 ; off-sheet ADC_EXT_VREF
AM263P_EQEP0_A: R328.1 ; off-sheet AM263P_EQEP0_A
AM263P_EQEP0_A_R: R328.2 U43.1(A1)
AM263P_EQEP0_B: R329.1 ; off-sheet AM263P_EQEP0_B
AM263P_EQEP0_B_R: R329.2 U43.3(A2)
AM263P_EQEP0_INDEX: R330.1 ; off-sheet AM263P_EQEP0_INDEX
AM263P_EQEP0_INDEX_R: R330.2 U43.4(A3)
AM263P_EQEP0_STROBE: R331.1 ; off-sheet AM263P_EQEP0_STROBE
AM263P_EQEP0_STROBE_R: R331.2 U43.5(A4)
AM263P_EQEP2_A: R332.1 ; off-sheet AM263P_EQEP2_A
AM263P_EQEP2_A_R: R332.2 U43.6(A5)
AM263P_EQEP2_B: R333.1 ; off-sheet AM263P_EQEP2_B
AM263P_EQEP2_B_R: R333.2 U43.7(A6)
AM263P_EQEP2_INDEX: R334.1 ; off-sheet AM263P_EQEP2_INDEX
AM263P_EQEP2_INDEX_R: R334.2 U43.8(A7)
AM263P_EQEP2_STROBE: R335.1 ; off-sheet AM263P_EQEP2_STROBE
AM263P_EQEP2_STROBE_R: R335.2 U43.9(A8)
AM263P_FSIRX1_CLK: J23.1 ; off-sheet AM263P_FSIRX1_CLK
AM263P_FSIRX1_DATA0: J23.5 ; off-sheet AM263P_FSIRX1_DATA0
AM263P_FSIRX1_DATA1: J23.7 ; off-sheet AM263P_FSIRX1_DATA1
AM263P_FSITX1_CLK: J23.2 ; off-sheet AM263P_FSITX1_CLK
AM263P_FSITX1_DATA0: J23.6 ; off-sheet AM263P_FSITX1_DATA0
AM263P_FSITX1_DATA1: J23.8 ; off-sheet AM263P_FSITX1_DATA1
AM263P_MCAN3_RX: R249.1 ; off-sheet AM263P_MCAN3_RX
AM263P_MCAN3_TX: U42.1(TXD) ; off-sheet AM263P_MCAN3_TX
AM263P_MCAN_STB: R248.2 ; off-sheet AM263P_MCAN_STB
CAN_STB: R244.1 R248.1 R250.2 U42.8(STB)
CANA_N: J33.1 R246.2 U42.6(CANL)
CANA_P: J33.3 R247.2 U42.7(CANH)
DAC_EXT_VREF: J18.2 ; off-sheet DAC_EXT_VREF
EQEP0_A: C214.1 J24.1 R236.1 U43.20(B1)
EQEP0_B: C215.2 J24.2 R237.1 U43.18(B2)
EQEP0_INDEX: C216.1 J24.3 R238.1 U43.17(B3)
EQEP0_STROBE: C220.1 J15.1 R242.1 U43.16(B4)
EQEP2_A: C217.1 J25.1 R239.1 U43.15(B5)
EQEP2_B: C218.2 J25.2 R240.1 U43.14(B6)
EQEP2_INDEX: C219.1 J25.3 R241.1 U43.13(B7)
EQEP2_STROBE: C221.1 J16.1 R243.1 U43.12(B8)
NetC222_1: C222.1 R246.1 R247.1
NetR249_2: R249.2 U42.4(RXD)

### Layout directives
differential pair: CANA_N, CANA_P
mark named MCAN_120: CANA_N, CANA_P

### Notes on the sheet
- Breakout Headers
- FSI Header
- eQEP0/SFDM1 Headers
- eQEP2/SFDM2 Headers
- C2000 LP Style FSI Breakout
- SFDM1 MUX'd signals
  - SDFM1_D0/CLK0
  - SDFM1_D1/CLK1
- SFDM2 MUX'd signals
  - SDFM2_D2/CLK2
  - SDFM2_D3/CLK3
- ADC/DAC External VREF Header
- MCAN3 PHY and Header
- eQEP Bi-Directional
- Level Translator

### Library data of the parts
C211-C213 C224 = CMP-0007469-4: CAP, CERM, 0.1 uF, 100 V, +/- 10%, X7R, 0603; Manufacturer: MuRata; TaMin_C: -55°C; Polarized: N; SizeAreaWB_mm2: 4.68; Value1: Unknown; U/M: EA; Value: 0.1uF; TaMax_C: 125°C; SizeZ_mm: 1; SizeX_mm: 1.6; SizeY_mm: 0.8; SizeArea_mm2: 1.28; AEC Category: Q200
C214 C216 C217 C219-C221 = CMP-0007173-4: CAP, CERM, 1000 pF, 50 V, +/- 5%, C0G/NP0, 0603; Manufacturer: MuRata; Value: 1000pF; U/M: EA; SizeAreaWB_mm2: 4.68; SizeX_mm: 1.6; SizeZ_mm: 1; SizeArea_mm2: 1.28; TaMax_C: 125°C; SizeY_mm: 0.8; Cap_F: 1nF; TaMin_C: -55°C; Value1: Unknown; AEC Category: Q200; Polarized: N
C215 C218 = CMP-0035320-1: Ceramic Capacitor 100pF ±5% 250VDC C0G 0603 Paper T/R; Manufacturer: Murata; TempCo: 30ppm/°C; Tolerance_%: 0.05%; SizeZ_mm: 0.8mm; AEC Qualified: No
C222 = CMP-0006692-2: CAP, CERM, 4700 pF, 50 V, +/- 10%, X7R, 0402; Manufacturer: MuRata; TaMin_C: -55°C; Polarized: N; SizeAreaWB_mm2: 3; Value1: Unknown; U/M: EA; Value: 4700pF; TaMax_C: 125°C; SizeZ_mm: 0.6; SizeX_mm: 1; SizeY_mm: 0.5; Cap_F: 4.7nF; AEC Category: Q200
C223 C225 C226 = CMP-0006659-2: as C243-C246 on sheet PROC171_Boosterpack_Headers
J15-J18 = CMP-0054566-1: as J9 on sheet PROC171_Boosterpack_Headers
J23 = CMP-0080722-2: Header, 2.54mm, 5x2, Gold, TH; Manufacturer: Sullins Connector Solutions; Pitch_mm: 2.54; Gender: Male; Cert_UL: Y; Current_A: 3A; Voltage_V: 1kV; Shrouded: N; Row_Count: 2
J24 J25 = CMP-0054597-1: Header, 2.54mm, 5x1, Tin, TH; Manufacturer: Sullins Connector Solutions; CNHeader: TRUE; Current_A: 3A; Green_Lifecycle: Not Set; Shrouded: N; Gender: Male; Green_REACh: Incomplete; Voltage_V: 1.8kV; Row_Count: 1; Pitch_mm: 2.54; CT: FALSE; Cert_UL: Y
J33 = CMP-0075352-1: Terminal Block, 3.5mm, 3x1, Tin, R/A, TH; Manufacturer: On-Shore Technology; CNHeader: False; Current_A: 10A; Green_Lifecycle: Not Set; Gender: Female; Cert_CSA: Y; Green_REACh: Incomplete; Voltage_V: 125V; Row_Count: 1; Pitch_mm: 3.5; CT: True
R236-R243 = CMP-0026702-1: RES, 49.9 k, 1%, 0.1 W, AEC-Q200 Grade 0, 0402; Manufacturer: Panasonic; Power_W: 100mW; TempCo: 100 ppm/C; Value_Code: 49k9; U/M: EA; Value: 49.9k; EIA_Code: E96; SizeX_mm: 1; SizeY_mm: 0.5; SizeZ_mm: 0.6; Value2: 0.1W; AEC Qualified: Y; VDC_V: 50V; AEC Grade: 0; AEC Category: Q200
R244 R250 = CMP-0025958-3: RES, 10.0 k, 1%, 0.063 W, AEC-Q200 Grade 0, 0402; Manufacturer: Vishay-Dale; Power_W: 63mW; TempCo: 100 ppm/C; Value_Code: 10k0; Value: 10.0k; EIA_Code: E96; Res_ohm: 10k; SizeX_mm: 1; SizeY_mm: 0.5; SizeZ_mm: 0.6; Value2: 0.063W; AEC Qualified: Y; VDC_V: 50V; AEC Category: Q200; AEC Grade: 0
R246 R247 = CMP-0026491-2: RES, 61.9, 1%, 0.063 W, AEC-Q200 Grade 0, 0402; Manufacturer: Vishay-Dale; Power_W: 63mW; TempCo: 100 ppm/C; Value_Code: 61R9; Value: 61.9; EIA_Code: E96; SizeX_mm: 1; SizeY_mm: 0.5; SizeZ_mm: 0.6; Value2: 0.063W; AEC Qualified: Y; VDC_V: 50V; AEC Category: Q200; AEC Grade: 0
R248 = CMP-0026992-3: as R231 on sheet PROC171_Ehernet_RJ45_2
R249 = CMP-0026880-3: RES, 22, 5%, 0.063 W, AEC-Q200 Grade 0, 0402; Manufacturer: Vishay-Dale; Power_W: 63mW; TempCo: 200 ppm/C; Value_Code: 22R0; Value: 22; EIA_Code: E24; SizeX_mm: 1; SizeY_mm: 0.5; SizeZ_mm: 0.6; Value2: 0.063W; AEC Qualified: Y; VDC_V: 50V; AEC Category: Q200; AEC Grade: 0
R328-R335 = CMP-0026299-2: RES, 33.2, 1%, 0.063 W, AEC-Q200 Grade 0, 0402; Manufacturer: Vishay-Dale; Power_W: 63mW; TempCo: 100 ppm/C; Value_Code: 33R2; Value: 33.2; EIA_Code: E96; SizeX_mm: 1; SizeY_mm: 0.5; SizeZ_mm: 0.6; Value2: 0.063W; AEC Qualified: Y; VDC_V: 50V; AEC Category: Q200; AEC Grade: 0
U42 = CMP-0079884-2: Automotive High Speed CAN Transceiver, DRB0008J (VSON-8); Alternate Manufacturer: Texas Instruments; Alternate PartNumber: TCAN1044VDRBRQ1; SizeX_mm: 3; AEC Category: Q200; SizeAreaWB_mm2: 16; SizeZ_mm: 1; SizeArea_mm2: 9; AEC Qualified: Y; CompType: IC
U43 = CMP-0074359-2: 8-Bit Bidirectional Voltage-Level Shifter with Auto Direction Sensing and +/-15-kV ESD Protect, RGY0020A (VQFN-20); Manufacturer: Texas Instruments; SizeZ_mm: 1.0; SizeX_mm: 3.5; SizeY_mm: 4.5; SizeArea_mm2: 15.75; CompType: IC; U/M: EA; SizeAreaWB_mm2: 24.75

## Sheet PROC171_IO_EXPANDER.SchDoc
size 431 x 279 mm; DocumentNumber: 23; SheetNumber: 23; SheetTotal: 27
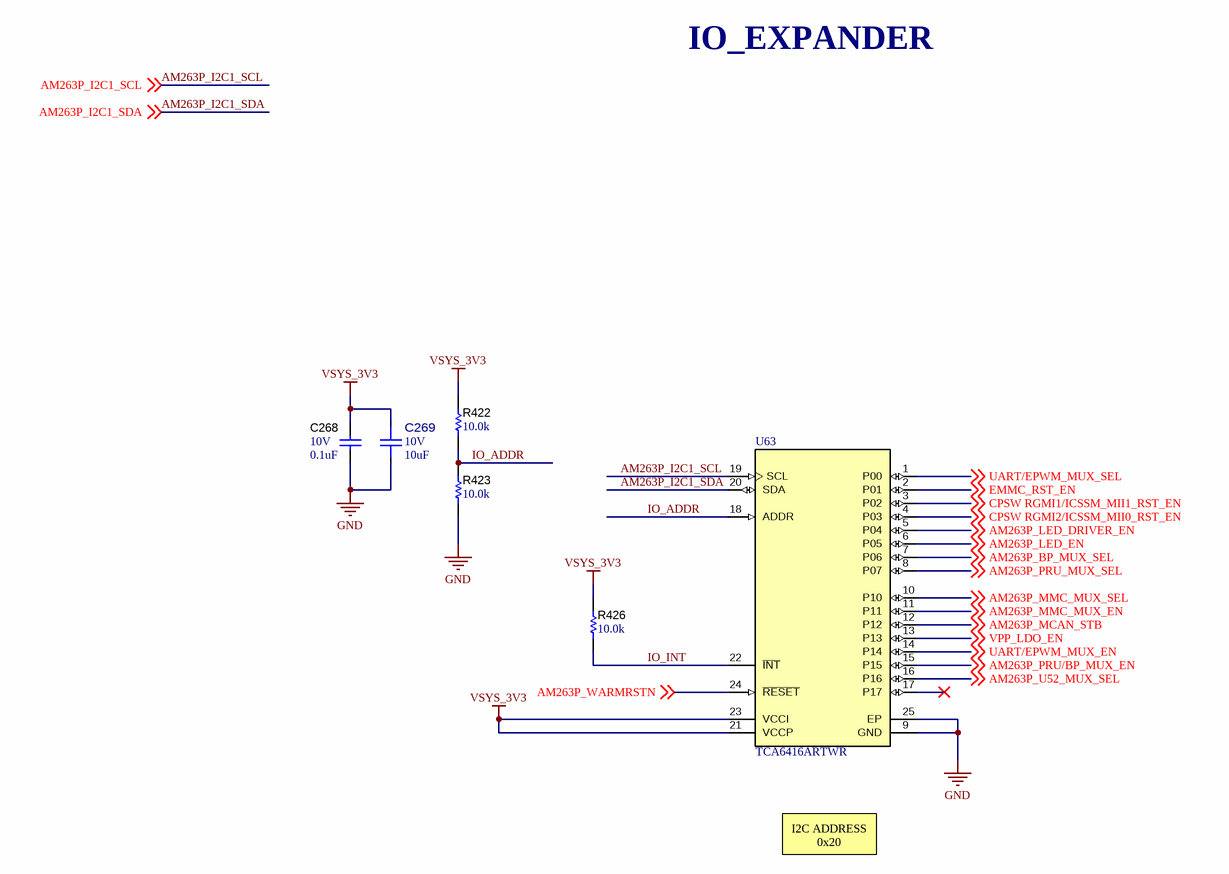
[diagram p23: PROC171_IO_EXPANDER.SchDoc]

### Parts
C268  VDC_V: 10V  ValueDisplayed: 0.1uF  [0402]  (hidden comment: 885012105010)
C269  ValueDisplayed: 10uF  VDC_V: 10V  [FP-KGM05CR51A106MH_0402-MFG]  (hidden comment: KGM05CR51A106MH)
R422  ValueDisplayed: 10.0k  [0402]  (hidden comment: ERJ-2RKF1002X)
R423  ValueDisplayed: 10.0k  [0402]  (hidden comment: ERJ-2RKF1002X)
R426  ValueDisplayed: 10.0k  [0402]  (hidden comment: ERJ-2RKF1002X)
U63  TCA6416ARTWR  [RTW0024B]

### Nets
GND: C268.2 C269.2 R423.1 U63.9(GND) U63.25(EP)
VSYS_3V3: C268.1 C269.1 R422.2 R426.2 U63.21(VCCP) U63.23(VCCI)
AM263P_BP_MUX_SEL: U63.7(P06) ; off-sheet AM263P_BP_MUX_SEL
AM263P_I2C1_SCL: U63.19(SCL) ; off-sheet AM263P_I2C1_SCL
AM263P_I2C1_SDA: U63.20(SDA) ; off-sheet AM263P_I2C1_SDA
AM263P_LED_DRIVER_EN: U63.5(P04) ; off-sheet AM263P_LED_DRIVER_EN
AM263P_LED_EN: U63.6(P05) ; off-sheet AM263P_LED_EN
AM263P_MCAN_STB: U63.12(P12) ; off-sheet AM263P_MCAN_STB
AM263P_MMC_MUX_EN: U63.11(P11) ; off-sheet AM263P_MMC_MUX_EN
AM263P_MMC_MUX_SEL: U63.10(P10) ; off-sheet AM263P_MMC_MUX_SEL
AM263P_PRU/BP_MUX_EN: U63.15(P15) ; off-sheet AM263P_PRU/BP_MUX_EN
AM263P_PRU_MUX_SEL: U63.8(P07) ; off-sheet AM263P_PRU_MUX_SEL
AM263P_U52_MUX_SEL: U63.16(P16) ; off-sheet AM263P_U52_MUX_SEL
AM263P_WARMRSTN: U63.24(~{RESET}) ; off-sheet AM263P_WARMRSTN
CPSW RGMI1/ICSSM_MII1_RST_EN: U63.3(P02) ; off-sheet CPSW RGMI1/ICSSM_MII1_RST_EN
CPSW RGMI2/ICSSM_MII0_RST_EN: U63.4(P03) ; off-sheet CPSW RGMI2/ICSSM_MII0_RST_EN
EMMC_RST_EN: U63.2(P01) ; off-sheet EMMC_RST_EN
IO_ADDR: R422.1 R423.2 U63.18(ADDR)
IO_INT: R426.1 U63.22(~{INT})
UART/EPWM_MUX_EN: U63.14(P14) ; off-sheet UART/EPWM_MUX_EN
UART/EPWM_MUX_SEL: U63.1(P00) ; off-sheet UART/EPWM_MUX_SEL
VPP_LDO_EN: U63.13(P13) ; off-sheet VPP_LDO_EN

Not connected (* = marked no-connect by the designer): U63 17(P17)*

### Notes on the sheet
- IO_EXPANDER
- I2C ADDRESS 0x20

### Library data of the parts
C268 = CMP-0006221-2: CAP, CERM, 0.1 uF, 10 V, +/- 20%, X5R, 0402; Manufacturer: Wurth Elektronik; TaMin_C: -55°C; Polarized: N; SizeAreaWB_mm2: 3; Value1: Unknown; U/M: EA; Value: 0.1uF; TaMax_C: 85°C; SizeZ_mm: 0.6; SizeX_mm: 1; SizeY_mm: 0.5; Cap_F: 100nF; AEC Category: Q200
C269 = CMP-0043010-1: 10 µF ±20% 10V Ceramic Capacitor X5R 0402 (1005 Metric); Manufacturer: KYOCERA AVX; AEC Qualified: No; Cap_F: 10µF; SizeZ_mm: 0.7mm; TempCo: 15%; Value: 10µF
R422 R423 R426 = CMP-0026658-1: as R298 on sheet PROC171_Boosterpack_Headers
U63 = CMP-0043175-2: Low-Voltage 16-Bit I2C and SMBus I/O Expander, 16 Outputs, 1.65 to 5.5 V, -40 to 85 degC, 24-pin QFN (RTW), Green (RoHS & no Sb/Br); Manufacturer: Texas Instruments; SubFamily: I2C IO Expander; VCC(Max)(V): 5.5; VCC(Min)(V): 1.65; No. of Outputs: 16; fSCLK(Max)(MHz): 400; 5V Tolerant I/O: Yes; I2C Address: 0100 00x

## Sheet PROC171_LED.SchDoc
size 431 x 279 mm; Date: Not shown in title block; ApprovedBy: Not shown in title block; CheckedBy: Not shown in title block; Author: Not shown in title block; CompanyName: Not shown in title block; Engineer: Not shown in title block; Organization: Not shown in title block; Address1: Not shown in title block; Address2: Not shown in title block; Address3: Not shown in title block; Address4: Not shown in title block; DocumentNumber: 24; Revision: Use project parameter SCH_Rev; SheetNumber: 24; SheetTotal: 27; PageSetup: Record=PageOptions¦CenterHorizontal=True¦CenterVertical=True¦PrintScale=1.00¦XCorrection=1.00¦YCorrection=1.00¦PrintKind=0¦BorderSize=5000000¦LeftOffset=0¦BottomOffset=0¦Orientation=2¦PaperLength=1000¦PaperWidth=1000¦Scale=100¦PaperSource=15¦PrintQuality=600¦MediaType=1¦DitherType=10¦PaperKind=Letter¦PrintScaleMode=1
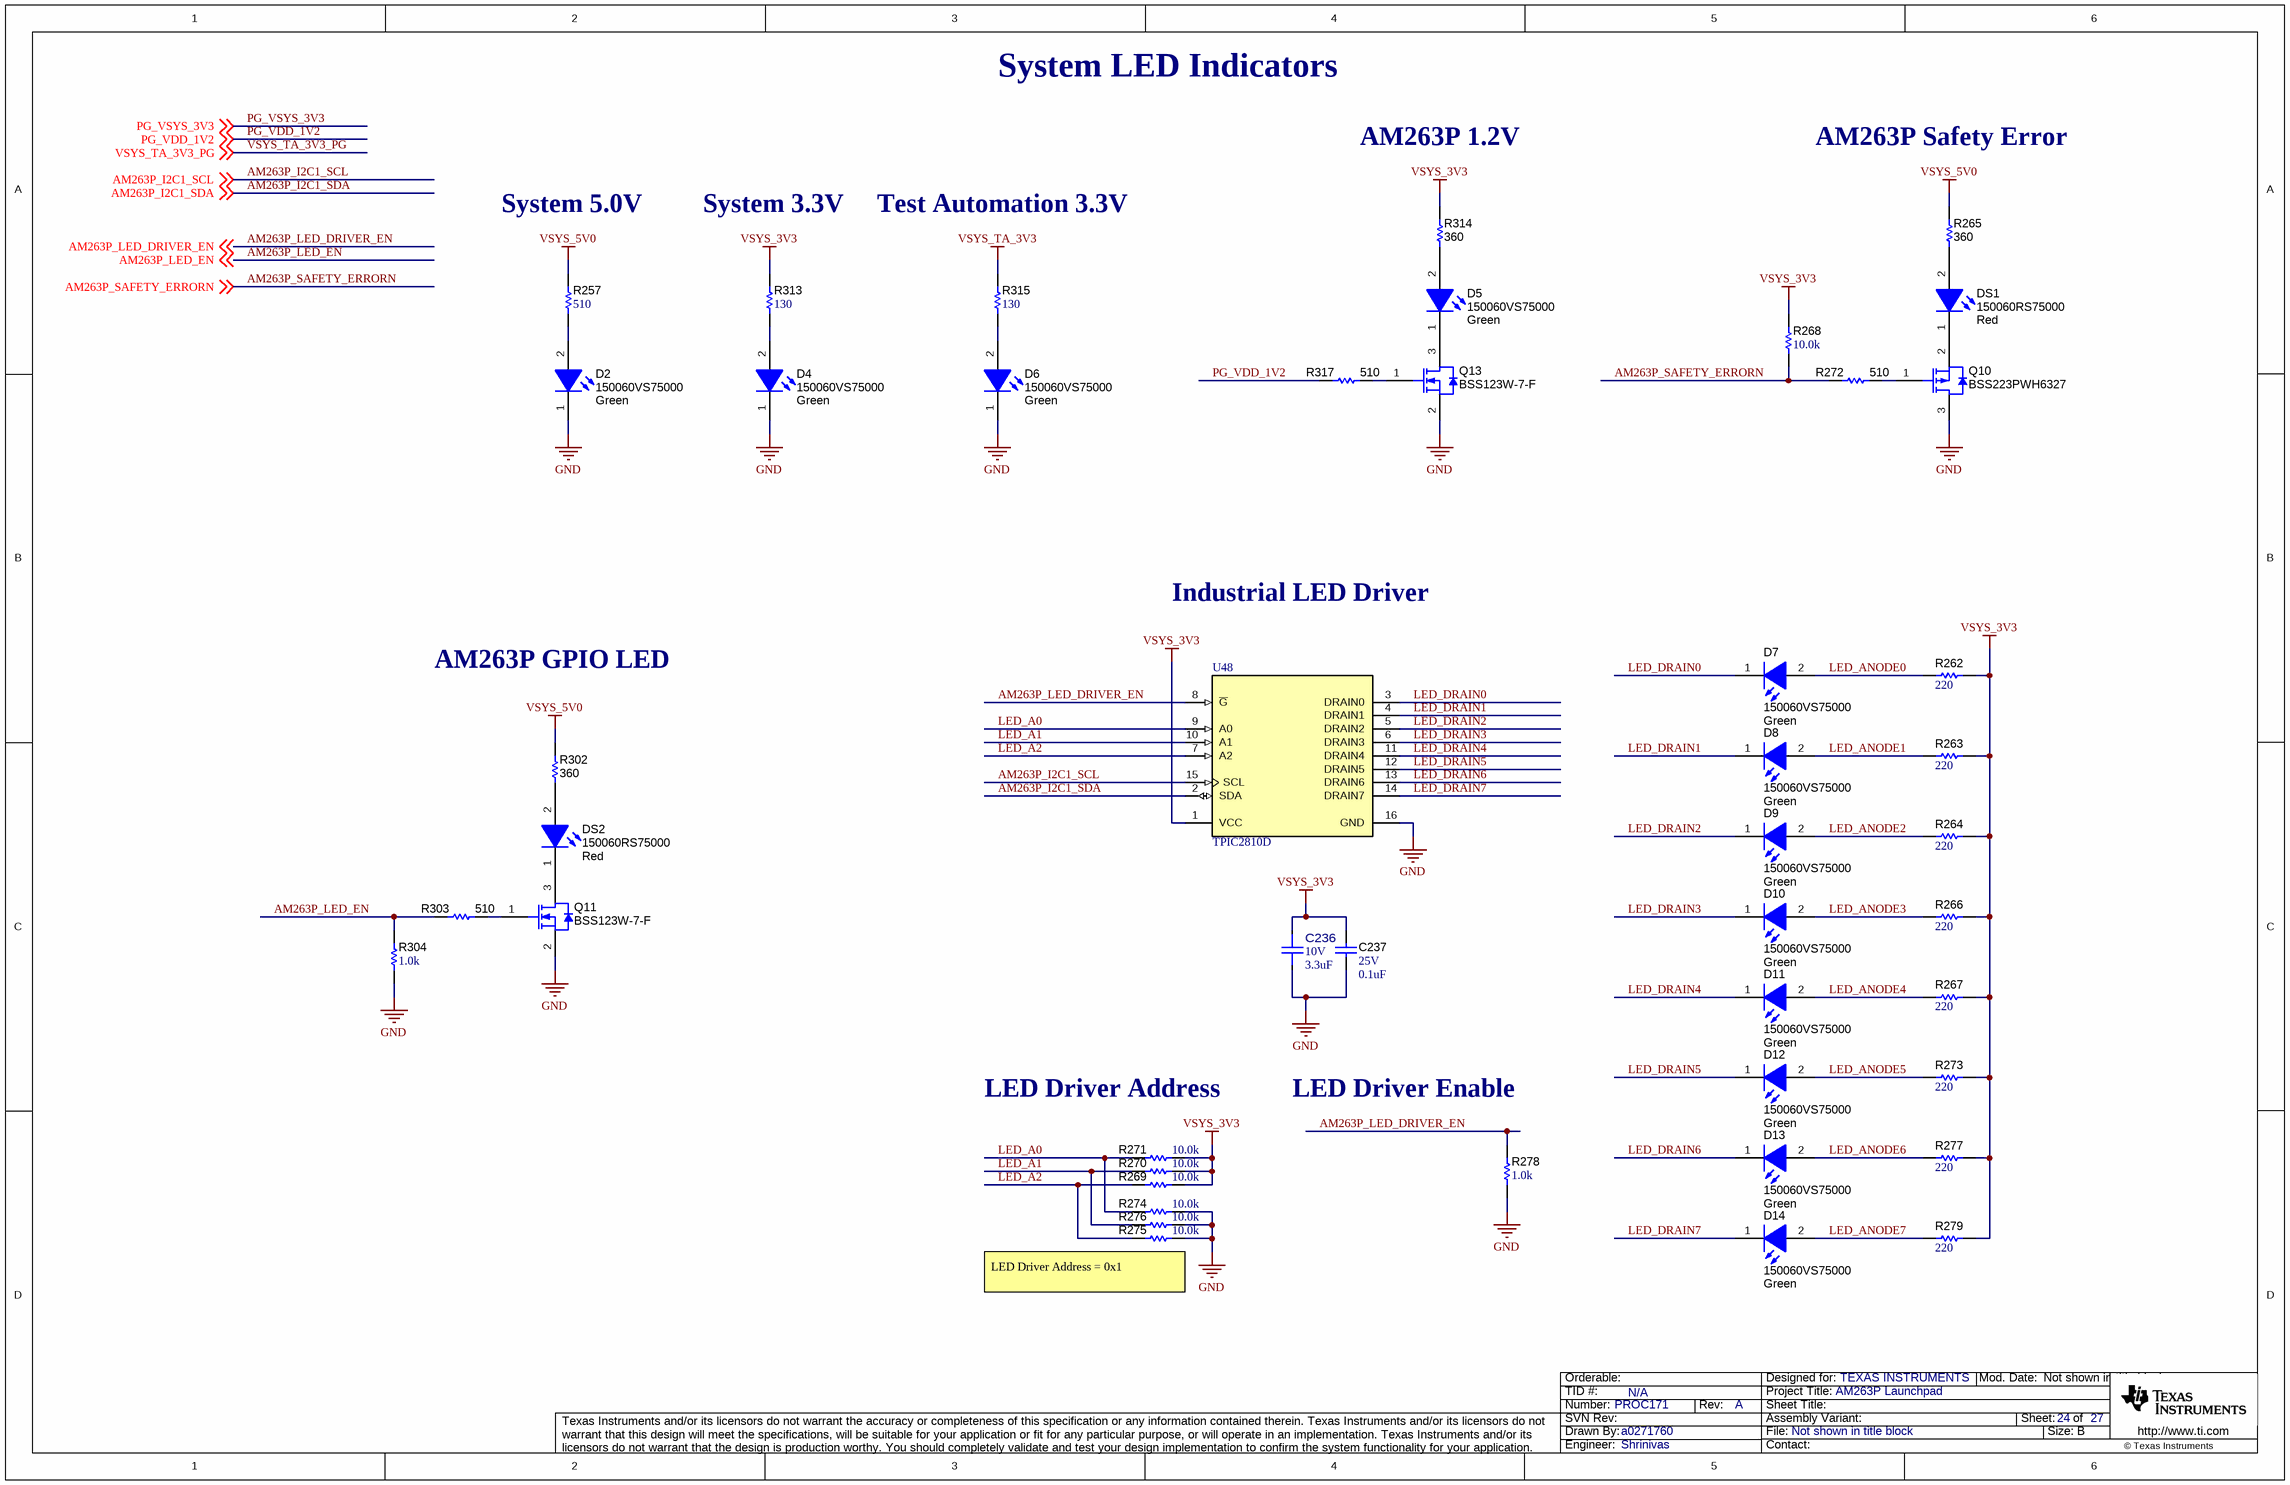
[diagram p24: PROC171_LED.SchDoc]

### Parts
C236  VDC_V: 10V  ValueDisplayed: 3.3uF  [FP-CL10A335KP8NNNC_0603-MFG]  (hidden comment: CL10A335KP8NNNC)
C237  VDC_V: 25V  ValueDisplayed: 0.1uF  [0402]  (hidden comment: GRM155R71E104KE14D)
D2  150060VS75000  value Green  [WL-SMCW_GREEN]
D4  150060VS75000  value Green  [WL-SMCW_GREEN]
D5  150060VS75000  value Green  [WL-SMCW_GREEN]
D6  150060VS75000  value Green  [WL-SMCW_GREEN]
D7  150060VS75000  value Green  [WL-SMCW_GREEN]
D8  150060VS75000  value Green  [WL-SMCW_GREEN]
D9  150060VS75000  value Green  [WL-SMCW_GREEN]
D10  150060VS75000  value Green  [WL-SMCW_GREEN]
D11  150060VS75000  value Green  [WL-SMCW_GREEN]
D12  150060VS75000  value Green  [WL-SMCW_GREEN]
D13  150060VS75000  value Green  [WL-SMCW_GREEN]
D14  150060VS75000  value Green  [WL-SMCW_GREEN]
DS1  150060RS75000  value Red  [WL-SMCW_RED]
DS2  150060RS75000  value Red  [WL-SMCW_RED]
Q10  BSS223PWH6327  [SOT-323]
Q11  BSS123W-7-F  [SOT-323]
Q13  BSS123W-7-F  [SOT-323]
R257  ValueDisplayed: 510  [0402]  (hidden comment: ERJ-2RKF5100X)
R262  ValueDisplayed: 220  [0402]  (hidden comment: ERJ-2RKF2200X)
R263  ValueDisplayed: 220  [0402]  (hidden comment: ERJ-2RKF2200X)
R264  ValueDisplayed: 220  [0402]  (hidden comment: ERJ-2RKF2200X)
R265  ValueDisplayed: 360  [0402L]  (hidden comment: ERJ-2GEJ361X)
R266  ValueDisplayed: 220  [0402]  (hidden comment: ERJ-2RKF2200X)
R267  ValueDisplayed: 220  [0402]  (hidden comment: ERJ-2RKF2200X)
R268  ValueDisplayed: 10.0k  [0402]  (hidden comment: ERJ-2RKF1002X)
R269  ValueDisplayed: 10.0k  [0402]  (hidden comment: ERJ-2RKF1002X)
R270  ValueDisplayed: 10.0k  [0402]  (hidden comment: ERJ-2RKF1002X)
R271  ValueDisplayed: 10.0k  [0402]  (hidden comment: ERJ-2RKF1002X)
R272  ValueDisplayed: 510  [0402L]  (hidden comment: ERJ-2GEJ511X)
R273  ValueDisplayed: 220  [0402]  (hidden comment: ERJ-2RKF2200X)
R274  ValueDisplayed: 10.0k  [0402]  (hidden comment: ERJ-2RKF1002X)
R275  ValueDisplayed: 10.0k  [0402]  (hidden comment: ERJ-2RKF1002X)
R276  ValueDisplayed: 10.0k  [0402]  (hidden comment: ERJ-2RKF1002X)
R277  ValueDisplayed: 220  [0402]  (hidden comment: ERJ-2RKF2200X)
R278  ValueDisplayed: 1.0k  [0402]  (hidden comment: ERJ-2GEJ102X)
R279  ValueDisplayed: 220  [0402]  (hidden comment: ERJ-2RKF2200X)
R302  ValueDisplayed: 360  [0402L]  (hidden comment: ERJ-2GEJ361X)
R303  ValueDisplayed: 510  [0402L]  (hidden comment: ERJ-2GEJ511X)
R304  ValueDisplayed: 1.0k  [0402]  (hidden comment: ERJ-2GEJ102X)
R313  ValueDisplayed: 130  [0402]  (hidden comment: CRCW0402130RFKED)
R314  ValueDisplayed: 360  [0402L]  (hidden comment: ERJ-2GEJ361X)
R315  ValueDisplayed: 130  [0402]  (hidden comment: CRCW0402130RFKED)
R317  ValueDisplayed: 510  [0402L]  (hidden comment: ERJ-2GEJ511X)
U48  TPIC2810D  [D0016A_N]

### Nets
GND: C236.2 C237.2 D2.1(K) D4.1(K) D6.1(K) Q10.3(D) Q11.2(S) Q13.2(S) R274.1 R275.1 R276.1 R278.1 R304.1 U48.16(GND)
VSYS_3V3: C236.1 C237.1 R262.2 R263.2 R264.2 R266.2 R267.2 R268.2 R269.1 R270.1 R271.1 R273.2 R277.2 R279.2 R313.2 R314.2 U48.1(VCC)
VSYS_5V0: R257.2 R265.2 R302.2
VSYS_TA_3V3: R315.2
AM263P_I2C1_SCL: U48.15(SCL) ; off-sheet AM263P_I2C1_SCL
AM263P_I2C1_SDA: U48.2(SDA) ; off-sheet AM263P_I2C1_SDA
AM263P_LED_DRIVER_EN: R278.2 U48.8(~{G}) ; off-sheet AM263P_LED_DRIVER_EN
AM263P_LED_EN: R303.1 R304.2 ; off-sheet AM263P_LED_EN
AM263P_SAFETY_ERRORN: R268.1 R272.1 ; off-sheet AM263P_SAFETY_ERRORN
LED_A0: R271.2 R274.2 U48.9(A0)
LED_A1: R270.2 R276.2 U48.10(A1)
LED_A2: R269.2 R275.2 U48.7(A2)
LED_ANODE0: D7.2(A) R262.1
LED_ANODE1: D8.2(A) R263.1
LED_ANODE2: D9.2(A) R264.1
LED_ANODE3: D10.2(A) R266.1
LED_ANODE4: D11.2(A) R267.1
LED_ANODE5: D12.2(A) R273.1
LED_ANODE6: D13.2(A) R277.1
LED_ANODE7: D14.2(A) R279.1
LED_DRAIN0: D7.1(K) U48.3(DRAIN0)
LED_DRAIN1: D8.1(K) U48.4(DRAIN1)
LED_DRAIN2: D9.1(K) U48.5(DRAIN2)
LED_DRAIN3: D10.1(K) U48.6(DRAIN3)
LED_DRAIN4: D11.1(K) U48.11(DRAIN4)
LED_DRAIN5: D12.1(K) U48.12(DRAIN5)
LED_DRAIN6: D13.1(K) U48.13(DRAIN6)
LED_DRAIN7: D14.1(K) U48.14(DRAIN7)
PG_VDD_1V2: R317.1 ; off-sheet PG_VDD_1V2
NetD2_2: D2.2(A) R257.1
NetD4_2: D4.2(A) R313.1
NetD5_1: D5.1(K) Q13.3(D)
NetD5_2: D5.2(A) R314.1
NetD6_2: D6.2(A) R315.1
NetDS1_1: DS1.1(K) Q10.2(S)
NetDS1_2: DS1.2(A) R265.1
NetDS2_1: DS2.1(K) Q11.3(D)
NetDS2_2: DS2.2(A) R302.1
NetQ10_1: Q10.1(G) R272.2
NetQ11_1: Q11.1(G) R303.2
NetQ13_1: Q13.1(G) R317.2

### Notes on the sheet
- System LED Indicators
- AM263P 1.2V
- AM263P Safety Error
- System 5.0V
- System 3.3V
- Test Automation 3.3V
- Industrial LED Driver
- AM263P GPIO LED
- LED Driver Address
- LED Driver Enable
- (near R275) LED Driver Address = 0x1

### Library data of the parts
C236 = CMP-0042976-1: Cap Ceramic 3.3uF 10V X5R ±10% Pad SMD 0603 +85°C T/R; Manufacturer: Samsung; TempCo: 15%; Value: 3.3µF; SizeZ_mm: 0.9mm; AEC Qualified: No
C237 = CMP-0006659-2: CAP, CERM, 0.1 uF, 25 V, +/- 10%, X7R, 0402; Manufacturer: MuRata; TaMin_C: -55°C; Polarized: N; SizeAreaWB_mm2: 3; Value1: Unknown; U/M: EA; Value: 0.1uF; TaMax_C: 125°C; SizeZ_mm: 0.6; SizeX_mm: 1; SizeY_mm: 0.5; Cap_F: 100nF; AEC Category: Q200
D2 D4-D14 = CMP-0002894-2: LED, Green, SMD; Manufacturer: Wurth Elektronik; Io_A: 20mA; Value1: W; Vf_V: 2V; Type: AlInGaP
DS1 DS2 = CMP-0002947-3: LED, Red, SMD; Manufacturer: Wurth Elektronik; Value1: 0.072W; Vf_V: 2V; Angle: 140; Tjmax_C: 85°C; Type: AlInGaP; Vr_V: 5V; Io_A: 30mA; Power_TotalModule: 72mW
Q10 = CMP-0000010-3: MOSFET, P-CH, -20 V, -0.39 A, SOT-323; Alternate Manufacturer: None; Manufacturer: Infineon Technologies; Value: -20V; Rdson45_ohm: 1.2; SizeX_mm: 2.2; AEC Category: Q101; ChMode: Enhancement; Vgs_V: -12V; Value1: 1; IdsMax_A: -390mA; ChType: P; SizeAreaWB_mm2: 10.24; QgTyp_nC: -0.5; SizeArea_mm2: 4.84; SizeZ_mm: 1.1
Q11 Q13 = CMP-0000948-2: MOSFET, N-CH, 100 V, 0.17 A, SOT-323; Alternate Manufacturer: None; Manufacturer: Diodes Inc.; SizeZ_mm: 1.1; ChType: N; Value1: 1; VdsMax_V: 100V; SizeX_mm: 2.2; Vgs_V: 20V; Value: 100V; Rdson45_ohm: 10; SizeArea_mm2: 4.84; AEC Category: Q101; IdsMax_A: 170mA; SizeAreaWB_mm2: 10.24; U/M: EA
R257 = CMP-0026704-1: RES, 510, 1%, 0.1 W, 0402; Manufacturer: Panasonic; Power_W: 100mW; TempCo: 100 ppm/C; Value_Code: 510R; U/M: EA; Value: 510; SizeX_mm: 1; SizeY_mm: 0.5; SizeZ_mm: 0.6; Value2: 0.1W; VDC_V: 50V; AEC Category: Q200
R262-R264 R266 R267 R273 R277 R279 = CMP-0026680-1: RES, 220, 1%, 0.1 W, AEC-Q200 Grade 0, 0402; Manufacturer: Panasonic; Power_W: 100mW; TempCo: 100 ppm/C; Value_Code: 220R; U/M: EA; Value: 220; SizeX_mm: 1; SizeY_mm: 0.5; SizeZ_mm: 0.6; Value2: 0.1W; AEC Qualified: Y; VDC_V: 50V; AEC Grade: 0; AEC Category: Q200
R265 R302 R314 = CMP-0078194-1: RES, 360, 5%, 0.1 W, AEC-Q200 Grade 0, 0402; Manufacturer: Panasonic; Value_Code: 360R; SizeArea_mm2: 0.5; AEC Qualified: Y; AEC Category: Q200; Value: 360; SizeZ_mm: 0.6; EIA_Code: E24; TempCo: 200 ppm/C; AEC Grade: 0; Power_W: 100mW; VDC_V: 50V; Value2: 0.1W; U/M: EA; SizeX_mm: 1
R268-R271 R274-R276 = CMP-0026658-1: as R298 on sheet PROC171_Boosterpack_Headers
R272 R303 R317 = CMP-0078212-1: RES, 510, 5%, 0.1 W, AEC-Q200 Grade 0, 0402; Manufacturer: Panasonic; Value_Code: 510R; SizeArea_mm2: 0.5; AEC Qualified: Y; AEC Category: Q200; Value: 510; SizeZ_mm: 0.6; EIA_Code: E24; TempCo: 200 ppm/C; AEC Grade: 0; Power_W: 100mW; VDC_V: 50V; Value2: 0.1W; U/M: EA; SizeX_mm: 1
R278 R304 = CMP-0078193-1: as R256 on sheet PROC171_Boosterpack_Headers
R313 R315 = CMP-0025998-3: RES, 130, 1%, 0.063 W, AEC-Q200 Grade 0, 0402; Manufacturer: Vishay-Dale; Power_W: 63mW; TempCo: 100 ppm/C; Value_Code: 130R; Value: 130; EIA_Code: E96; SizeX_mm: 1; SizeY_mm: 0.5; SizeZ_mm: 0.6; Value2: 0.063W; AEC Qualified: Y; VDC_V: 50V; AEC Category: Q200; AEC Grade: 0
U48 = CMP-0044782-1: 8-Bit LED Driver with I2C Interface, D0016A, TUBE; Manufacturer: Texas Instruments; IO(PEAK)(A): 0.21; Priority (type 2): 1; rDS(on)(Ohms): 5; VDS(Max)(V): 40; IO(CONT)(A): 0.1; ICC(uA): 620; tPLH(ns): 1150; Rating: Catalog

## Sheet PROC171_XDS110_1.SchDoc: XDS110 JTAG/USB-to-UART Bridge
size 431 x 279 mm; Date: Not shown in title block; ApprovedBy: Not shown in title block; CheckedBy: Not shown in title block; Author: Not shown in title block; CompanyName: Not shown in title block; Engineer: Not shown in title block; Organization: Not shown in title block; Address1: Not shown in title block; Address2: Not shown in title block; Address3: Not shown in title block; Address4: Not shown in title block; DocumentNumber: 25; Revision: Use project parameter SCH_Rev; SheetNumber: 25; SheetTotal: 27; PageSetup: Record=PageOptions¦CenterHorizontal=True¦CenterVertical=True¦PrintScale=1.00¦XCorrection=1.00¦YCorrection=1.00¦PrintKind=0¦BorderSize=5000000¦LeftOffset=0¦BottomOffset=0¦Orientation=2¦PaperLength=1000¦PaperWidth=1000¦Scale=100¦PaperSource=15¦PrintQuality=600¦MediaType=1¦DitherType=10¦PaperKind=Letter¦PrintScaleMode=1
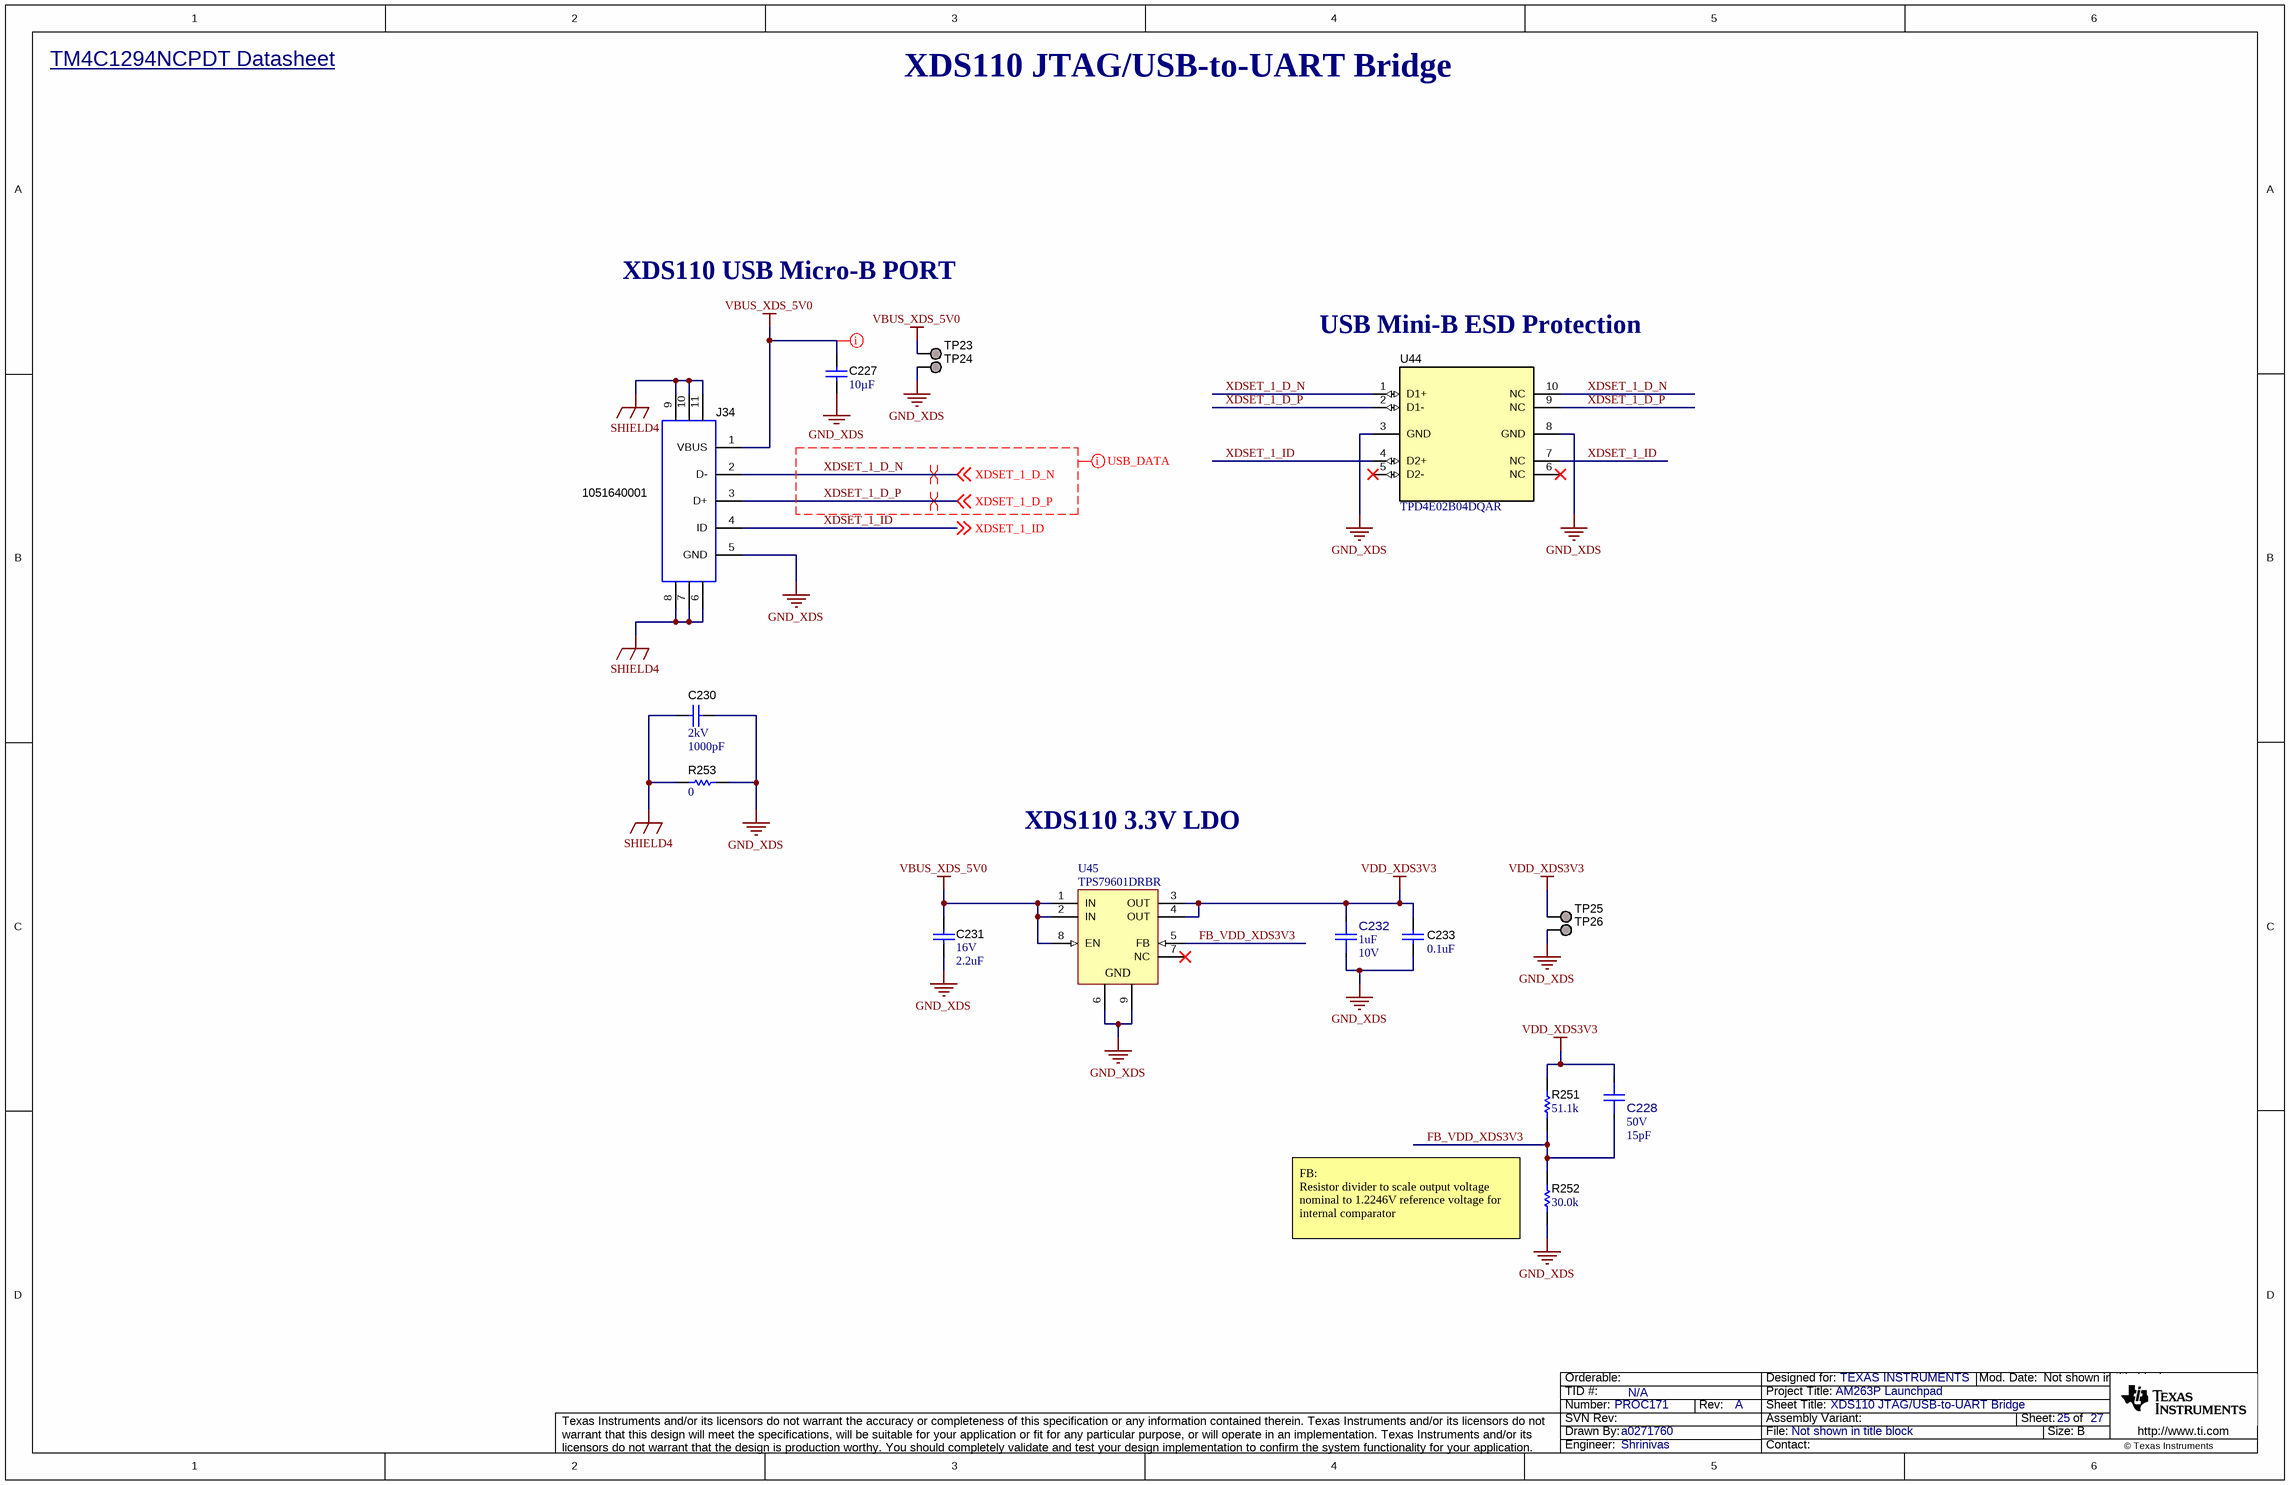
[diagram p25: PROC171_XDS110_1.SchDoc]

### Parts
C227  Cap_F: 10µF  [0805_HV]  (hidden comment: GRM21BZ71E106KE15L)
C228  VDC_V: 50V  ValueDisplayed: 15pF  [FP-GJM1555C1H150FB01D_0402-MFG]  (hidden comment: GJM1555C1H150FB01D)
C230  VDC_V: 2kV  ValueDisplayed: 1000pF  [1808]  (hidden comment: GR442QR73D102KW01L)
C231  VDC_V: 16V  ValueDisplayed: 2.2uF  [0402]  (hidden comment: GRM155C81C225KE11D)
C232  ValueDisplayed: 1uF  VDC_V: 10V  [FP-GRM155C71A105KE11D_0402-MFG]  (hidden comment: GRM155C71A105KE11D)
C233  ValueDisplayed: 0.1uF  [0402]  (hidden comment: GRM155R71E104KE14D)
J34  1051640001  [Molex_1051640001]
R251  ValueDisplayed: 51.1k  [0402]  (hidden comment: CRCW040251K1FKED)
R252  ValueDisplayed: 30.0k  [0402]  (hidden comment: CRCW040230K0FKED)
R253  ValueDisplayed: 0  [0805_HV]  (hidden comment: ERJ-6GEY0R00V)
TP23  TESTPOINT  [TP_25MIL-SMT]  (value not drawn)  (no BOM)
TP24  TESTPOINT  [TP_25MIL-SMT]  (value not drawn)  (no BOM)
TP25  TESTPOINT  [TP_25MIL-SMT]  (value not drawn)  (no BOM)
TP26  TESTPOINT  [TP_25MIL-SMT]  (value not drawn)  (no BOM)
U44  TPD4E02B04DQAR  [DQA0010A]
U45  TPS79601DRBR  [DRB0008B]

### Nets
GND_XDS: C227.2 C230.1 C231.2 C232.1 C233.1 J34.5(GND) R252.1 R253.2 TP24.1 TP26.1 U44.3(GND) U44.8(GND) U45.6(GND) U45.9(GND)
SHIELD4: C230.2 J34.6 J34.7 J34.8 J34.9 J34.10 J34.11 R253.1
VBUS_XDS_5V0: C227.1 C231.1 J34.1(VBUS) TP23.1 U45.1(IN) U45.2(IN) U45.8(EN)
VDD_XDS3V3: C228.2 C232.2 C233.2 R251.2 TP25.1 U45.3(OUT) U45.4(OUT)
FB_VDD_XDS3V3: C228.1 R251.1 R252.2 U45.5(FB)
XDSET_1_D_N: J34.2(D-) U44.1(D1+) U44.10(NC) ; off-sheet XDSET_1_D_N
XDSET_1_D_P: J34.3(D+) U44.2(D1-) U44.9(NC) ; off-sheet XDSET_1_D_P
XDSET_1_ID: J34.4(ID) U44.4(D2+) U44.7(NC) ; off-sheet XDSET_1_ID

Not connected (* = marked no-connect by the designer): U44 5(D2-)* 6(NC)*; U45 7(NC)*

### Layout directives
differential pair: XDSET_1_D_N, XDSET_1_D_P
net class POWER: VBUS_XDS_5V0
mark named USB_DATA: XDSET_1_D_N, XDSET_1_D_P

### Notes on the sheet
- TM4C1294NCPDT Datasheet <http://www.ti.com/lit/ds/symlink/tm4c1294ncpdt.pdf>
- XDS110 JTAG/USB-to-UART Bridge
- XDS110 USB Micro-B PORT
- USB Mini-B ESD Protection
- XDS110 3.3V LDO
- (near R252) FB:
  Resistor divider to scale output voltage nominal to 1.2246V reference voltage for internal comparator

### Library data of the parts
C227 = CMP-0008378-2: CAP, CERM, 10 uF, 25 V, +/- 10%, X7R, 0805; Manufacturer: MuRata; TaMin_C: -55°C; Polarized: N; SizeAreaWB_mm2: 6.75; Value1: Unknown; U/M: EA; Value: 10uF; TaMax_C: 125°C; SizeZ_mm: 1.45; SizeX_mm: 2; SizeY_mm: 1.25; Cap_Case: 0805; Value2: 25V; SizeArea_mm2: 2.5; AEC Category: Q200
C228 = CMP-0035231-1: Multi-Layer Ceramic Capacitor 15pF C0G  ±1% 0402 Paper T/R; Manufacturer: Murata; TempCo: 30ppm/°C; SizeZ_mm: 0.55mm; AEC Qualified: No
C230 = CMP-0009436-2: as C247 on sheet PROC171_Ehernet_RJ45_2
C231 = CMP-0006526-2: CAP, CERM, 2.2 uF, 16 V, +/- 10%, X6S, 0402; Manufacturer: MuRata; TaMin_C: -55°C; Polarized: N; SizeAreaWB_mm2: 3; Value1: Unknown; U/M: EA; Value: 2.2uF; TaMax_C: 105°C; SizeZ_mm: 0.6; SizeX_mm: 1; SizeY_mm: 0.5; Cap_F: 2.2µF; AEC Category: Q200
C232 = CMP-0035346-1: 1µF ±10% 10V Ceramic Capacitor X7S 0402 (1005 Metric); Manufacturer: Murata; AEC Qualified: No; SizeZ_mm: 0.6mm; TempCo: 22%
C233 = CMP-0006659-2: as C243-C246 on sheet PROC171_Boosterpack_Headers
J34 = CMP-0055311-1: Receptacle, USB 2.0, Micro B, 5 Position, R/A, SMT; Manufacturer: Molex; CNHeader: FALSE; Current_A: 1.8A; Gender: Female; Voltage_V: 30V; Pitch_mm: 0.65; ContactFinish: Gold; CT: TRUE; Cert_UL: Y
R251 = CMP-0026437-2: RES, 51.1 k, 1%, 0.063 W, AEC-Q200 Grade 0, 0402; Manufacturer: Vishay-Dale; Power_W: 63mW; TempCo: 100 ppm/C; Value_Code: 51k1; Value: 51.1k; EIA_Code: E96; SizeX_mm: 1; SizeY_mm: 0.5; SizeZ_mm: 0.6; Value2: 0.063W; AEC Qualified: Y; VDC_V: 50V; AEC Category: Q200; AEC Grade: 0
R252 = CMP-0078244-2: RES, 30.0 k, 1%, 0.063 W, AEC-Q200 Grade 0, 0402; Manufacturer: Vishay-Dale; Power_W: 63mW; Green_Lifecycle: Active; TempCo: 100 ppm/C; Value_Code: 30k0; Green_REACh: Passed; Value: 30.0k; Res_ohm: 30k; SizeX_mm: 1; SizeY_mm: 0.5; SizeZ_mm: 0.6; Value2: 0.063W; AEC Qualified: Y; VDC_V: 50V; AEC Grade: 0; AEC Category: Q200
R253 = CMP-0020616-3: RES, 0, 5%, 0.125 W, AEC-Q200 Grade 0, 0805; Manufacturer: Panasonic; Power_W: 125mW; TempCo: 600 ppm/C; Value_Code: 0000; Value: 0; EIA_Code: E24; SizeX_mm: 2; SizeY_mm: 1.25; SizeZ_mm: 1.45; Value2: 0.125W; SizeArea_mm2: 2.5; AEC Qualified: Y; VDC_V: 150V; AEC Category: Q200; SizeAreaWB_mm2: 6.75
TP23-TP26 = CMP-0078143-3: TEST POINT.  No entry in BOM.
U44 = CMP-0073612-3: 4-Channel ESD Protection Diode for USB Type-C and HDMI 2.0, DQA0010A (USON-10); Alternate Manufacturer: Texas Instruments; Green_Lifecycle: Active; SizeAreaWB_mm2: 7.0; Green_REACh: Passed; SizeZ_mm: 0.55; SizeX_mm: 1.0; SizeY_mm: 2.5; CompType: IC; AEC Category: Q200; AEC Qualified: Y
U45 = CMP-0036402-3: Single Output High PSRR LDO, 1 A, Adjustable 1.2 to 5.5 V Output, 2.7 to 5.5 V Input, 8-pin SON (DRB), -40 to 125 degC, Green (RoHS & no Sb/Br); Manufacturer: Texas Instruments; Vin(Min)(V): 2.7; Vout Adj(Max)(V): 5.5; Vout Adj(Min)(V): 1.2; Accuracy(%): 2; SubFamily: Single Channel LDO; Iq(Typ)(mA): 0.26; Vdo(Typ)(mV): 250; Iout(Max)(A): 1; AEC Category: Q200; AEC Qualified: N; CompType: IC; SizeAreaWB_mm2: 16.0; SizeArea_mm2: 9.0; SizeX_mm: 3.0; SizeZ_mm: 1.0

## Sheet PROC171_Hardware.SchDoc
size 431 x 279 mm; Date: Not shown in title block; ApprovedBy: Not shown in title block; CheckedBy: Not shown in title block; Author: Not shown in title block; CompanyName: Not shown in title block; Engineer: Not shown in title block; Organization: Not shown in title block; Address1: Not shown in title block; Address2: Not shown in title block; Address3: Not shown in title block; Address4: Not shown in title block; DocumentNumber: 27; Revision: Use project parameter SCH_Rev; SheetNumber: 27; SheetTotal: 27; PageSetup: Record=PageOptions¦CenterHorizontal=True¦CenterVertical=True¦PrintScale=1.00¦XCorrection=1.00¦YCorrection=1.00¦PrintKind=0¦BorderSize=5000000¦LeftOffset=0¦BottomOffset=0¦Orientation=2¦PaperLength=1000¦PaperWidth=1000¦Scale=100¦PaperSource=15¦PrintQuality=600¦MediaType=1¦DitherType=10¦PaperKind=Letter¦PrintScaleMode=1
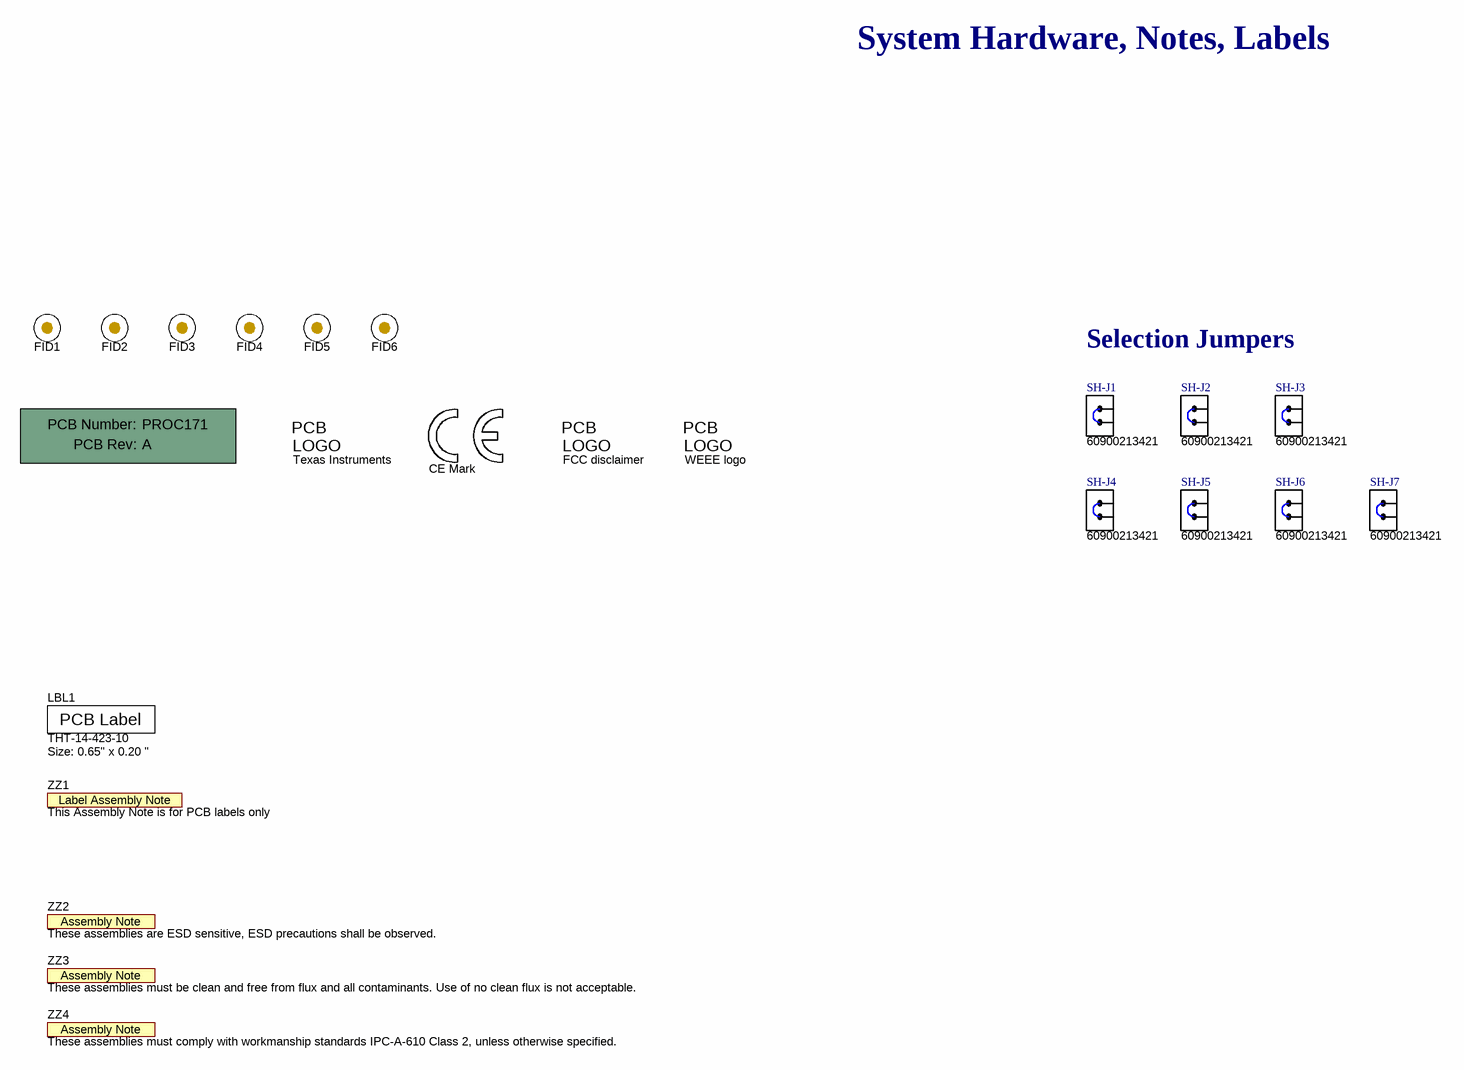
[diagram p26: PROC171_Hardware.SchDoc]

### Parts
!PCB1  Printed Circuit Board  (value not drawn)  (mechanical)
FID1  Fiducial  [Fiducial10-20]  (value not drawn)  (no BOM)
FID2  Fiducial  [Fiducial10-20]  (value not drawn)  (no BOM)
FID3  Fiducial  [Fiducial10-20]  (value not drawn)  (no BOM)
FID4  Fiducial  [Fiducial10-20]  (value not drawn)  (no BOM)
FID5  Fiducial  [Fiducial10-20]  (value not drawn)  (no BOM)
FID6  Fiducial  [Fiducial10-20]  (value not drawn)  (no BOM)
LBL1  THT-14-423-10  Note: Size: 0.65" x 0.20 "  [Label_650x200]
Logo1  CE Mark  [CE_Mark_5mm]  (no BOM)
Logo2  Texas Instruments  [TI_Stacked_Overlay_Small]  (no BOM)
Logo3  FCC disclaimer  [FCC_disclaimer]  (no BOM)
Logo4  WEEE logo  [WEEE_Minimum]  (no BOM)
SH-J1  60900213421  [Wurth_60900213421]
SH-J2  60900213421  [Wurth_60900213421]
SH-J3  60900213421  [Wurth_60900213421]
SH-J4  60900213421  [Wurth_60900213421]
SH-J5  60900213421  [Wurth_60900213421]
SH-J6  60900213421  [Wurth_60900213421]
SH-J7  60900213421  [Wurth_60900213421]
ZZ1  This Assembly Note is for PCB labels only  [AssemblyNoteLabel]  (no BOM)
ZZ2  These assemblies are ESD sensitive, ESD precautions shall be observed.  [AssemblyNote]  (no BOM)
ZZ3  These assemblies must be clean and free from flux and all contaminants. Use of no clean flux is not acceptable.  [AssemblyNote]  (no BOM)
ZZ4  These assemblies must comply with workmanship standards IPC-A-610 Class 2, unless otherwise specified.  [AssemblyNote]  (no BOM)

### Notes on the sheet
- System Hardware, Notes, Labels
- Selection Jumpers

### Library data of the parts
!PCB1 = CMP-0003618-2: Manufacturer: Any; PartNumber: PROC171
FID1-FID6 = CMP-0077181-1: Fiducial mark.  There is nothing to buy or mount.
LBL1 = CMP-0003625-1: Thermal Transfer Printable Labels, 0.650" W x 0.200" H - 10,000 per roll; Manufacturer: Brady; CompType: Label
Logo1 = CMP-0074844-1: SymbolCreator: a0412235
Logo2 = CMP-0074838-1: Texas Instrument Corporate Signature; SymbolCreator: a0412235; Lib Reference: TI_Logo; Library Reference: Logo
Logo3 = CMP-0074847-1: FCC_disclaimer; Library Reference: Logo
Logo4 = CMP-0074769-1
SH-J1-SH-J7 = CMP-0003761-2: Shunt, 2.54mm, Gold, Black; Manufacturer: Wurth Elektronik
ZZ1 = CMP-0003616-3
ZZ2 = CMP-0077236-1
ZZ3 = CMP-0077237-1
ZZ4 = CMP-0077238-1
